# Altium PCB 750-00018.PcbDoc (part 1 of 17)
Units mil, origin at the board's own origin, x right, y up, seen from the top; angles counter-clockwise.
Board outline 7086.64 x 6299.21 mil, 8 copper layers (Top Layer, L2, L3, L4, L5, L6, L7, Bottom Layer), stack 60.6 mil thick; 1356 components, 1054 nets, 4851 pads, 4296 vias.
Unrouted connection lines stored in the file: 12.
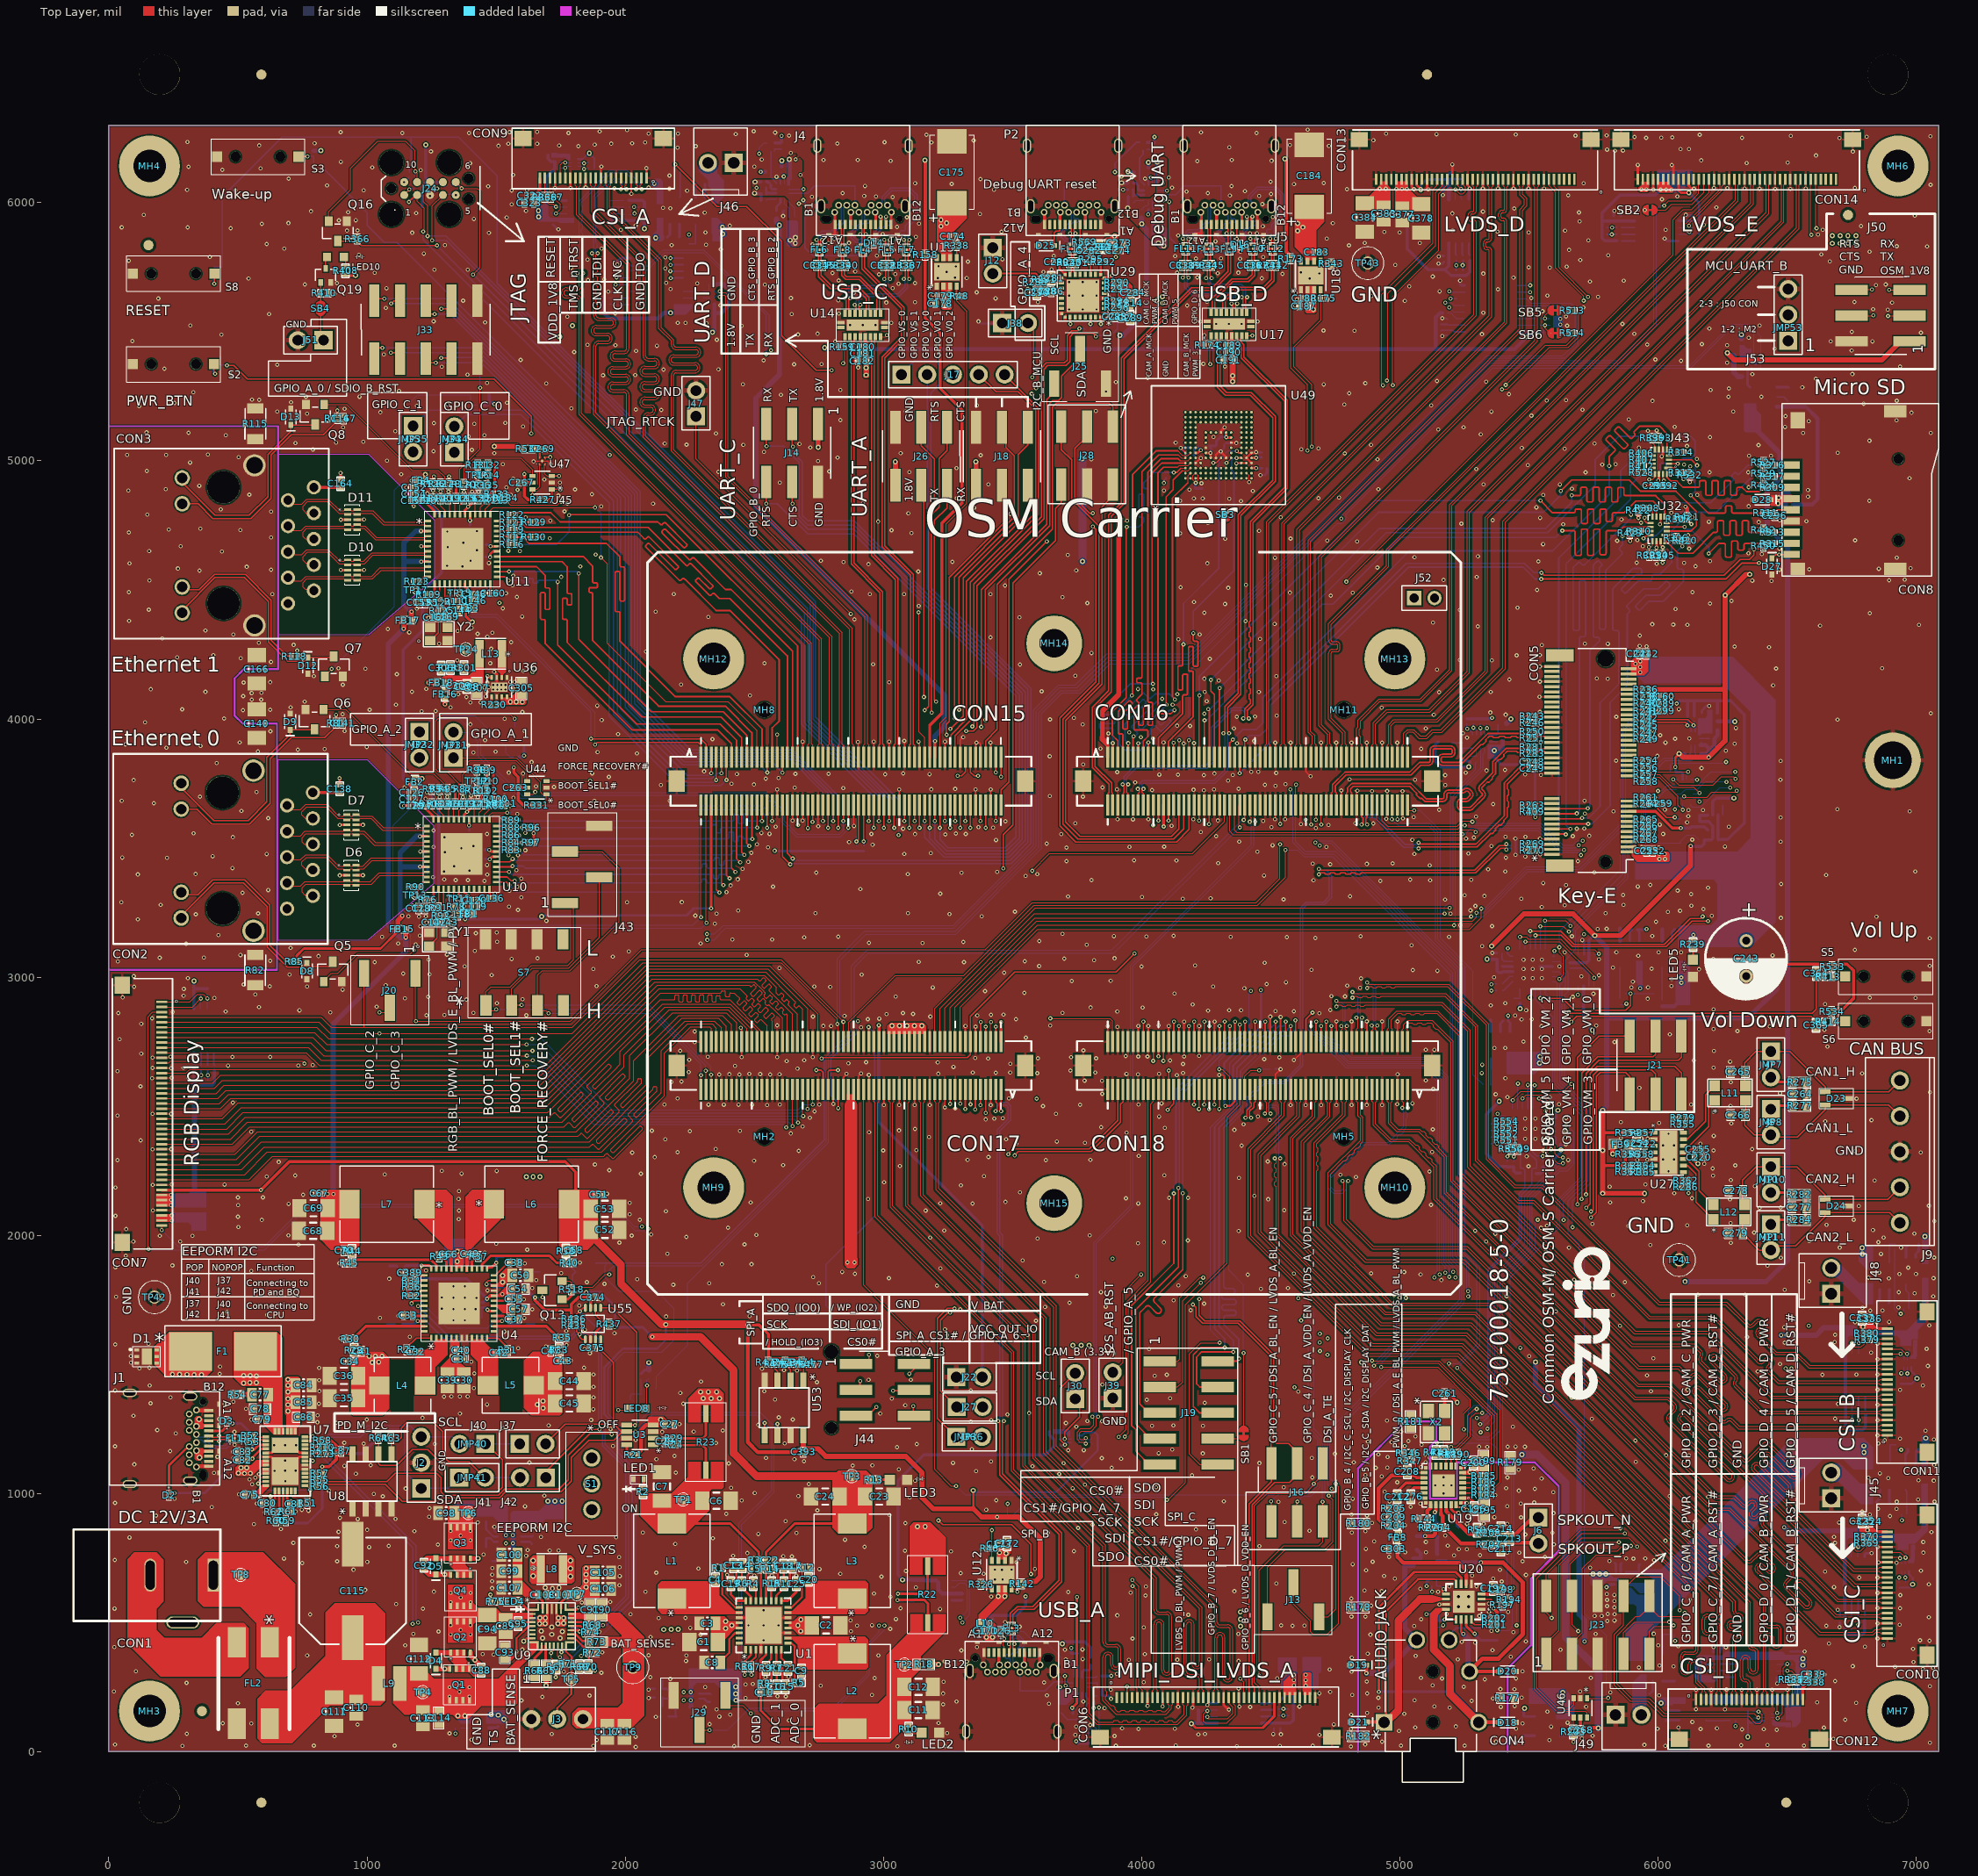
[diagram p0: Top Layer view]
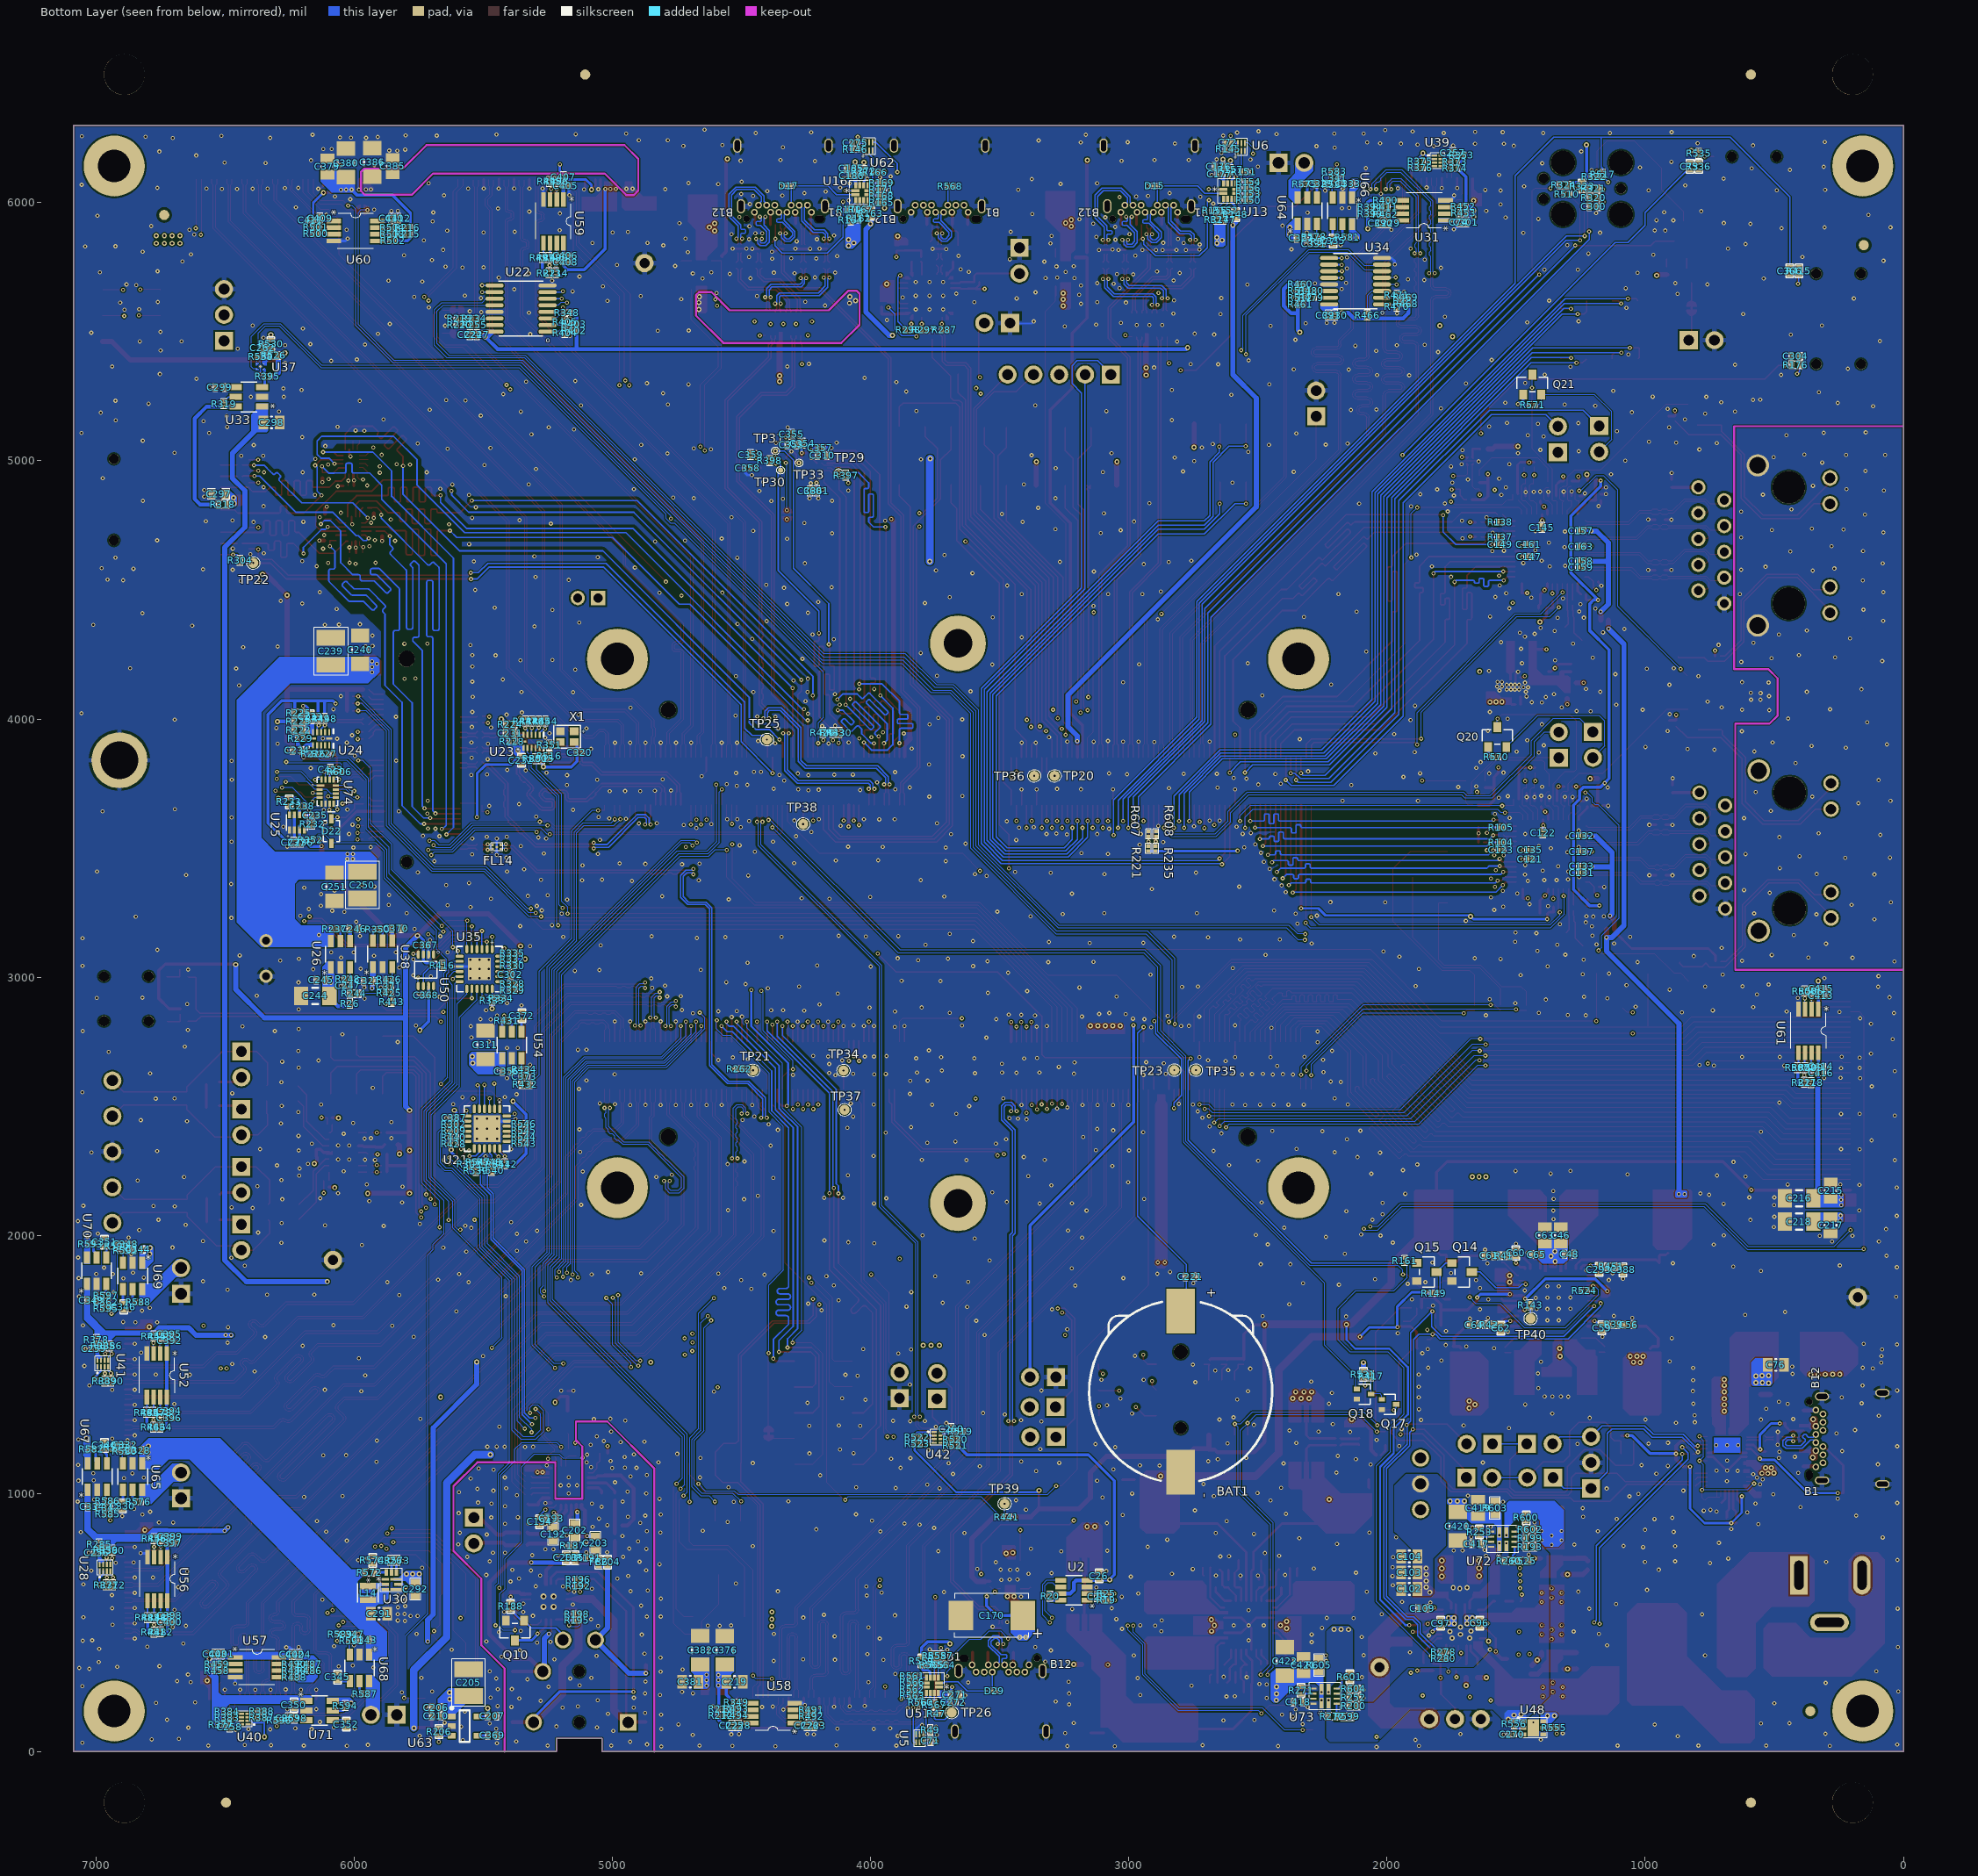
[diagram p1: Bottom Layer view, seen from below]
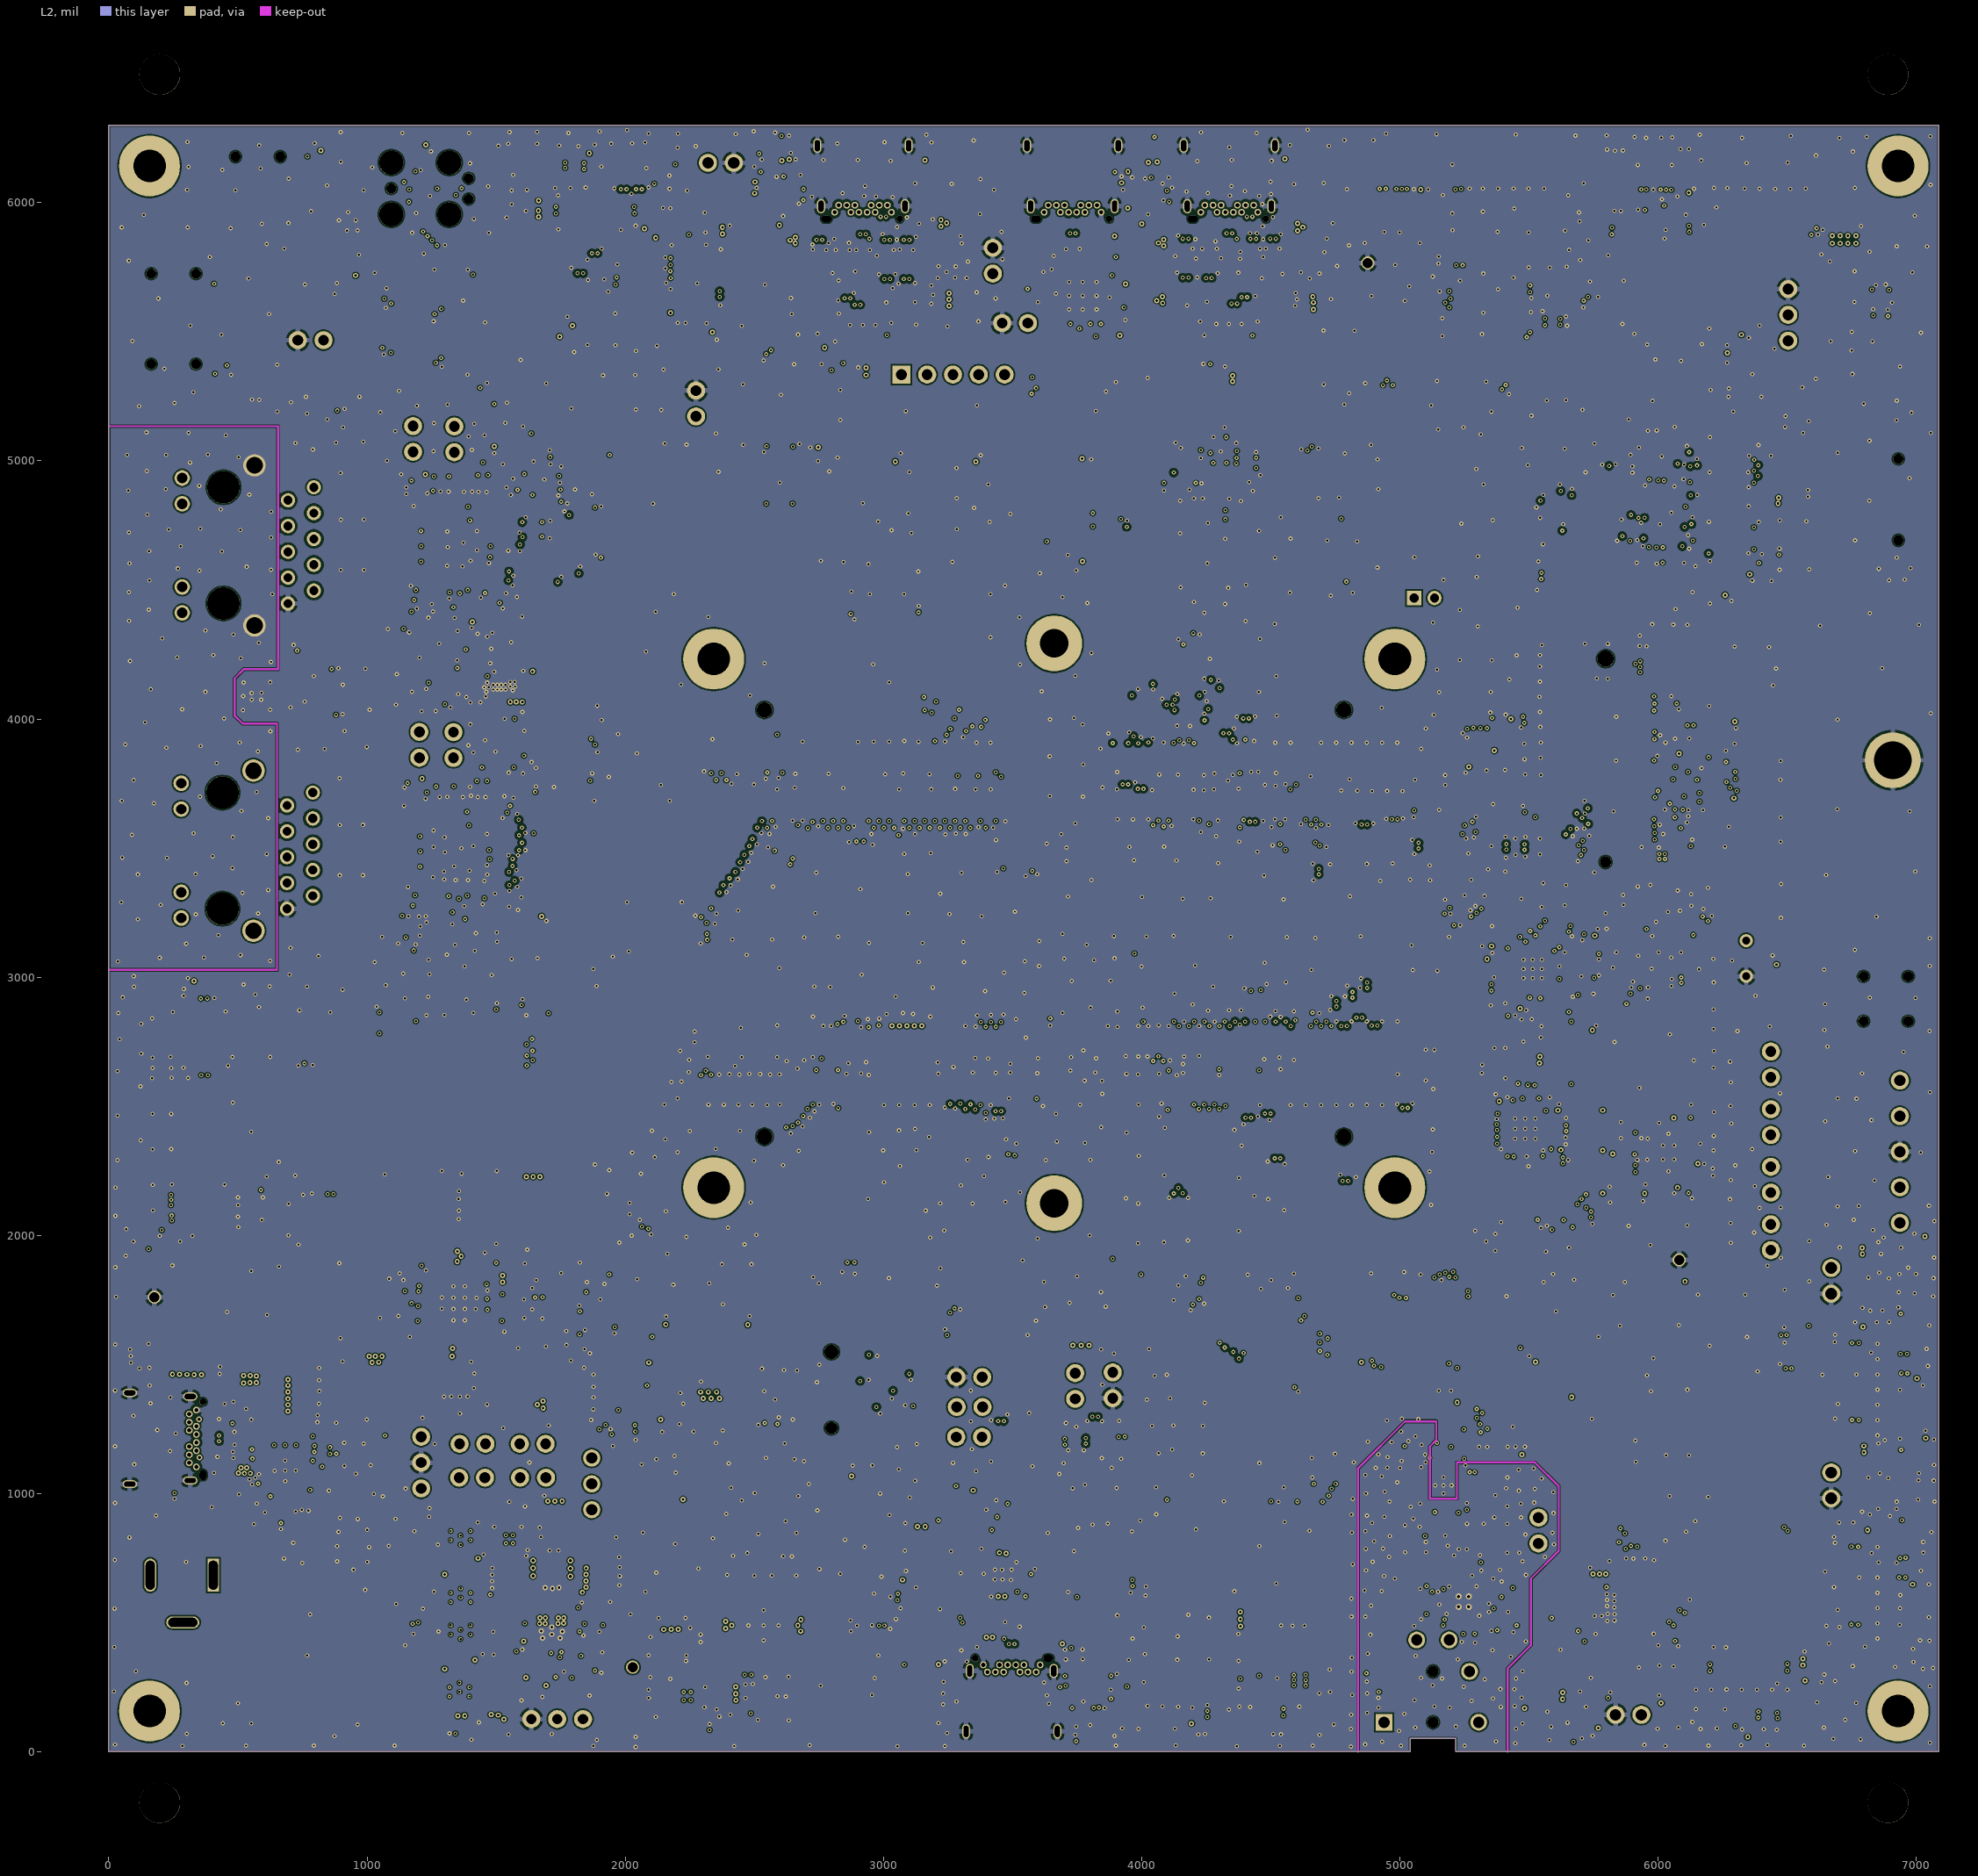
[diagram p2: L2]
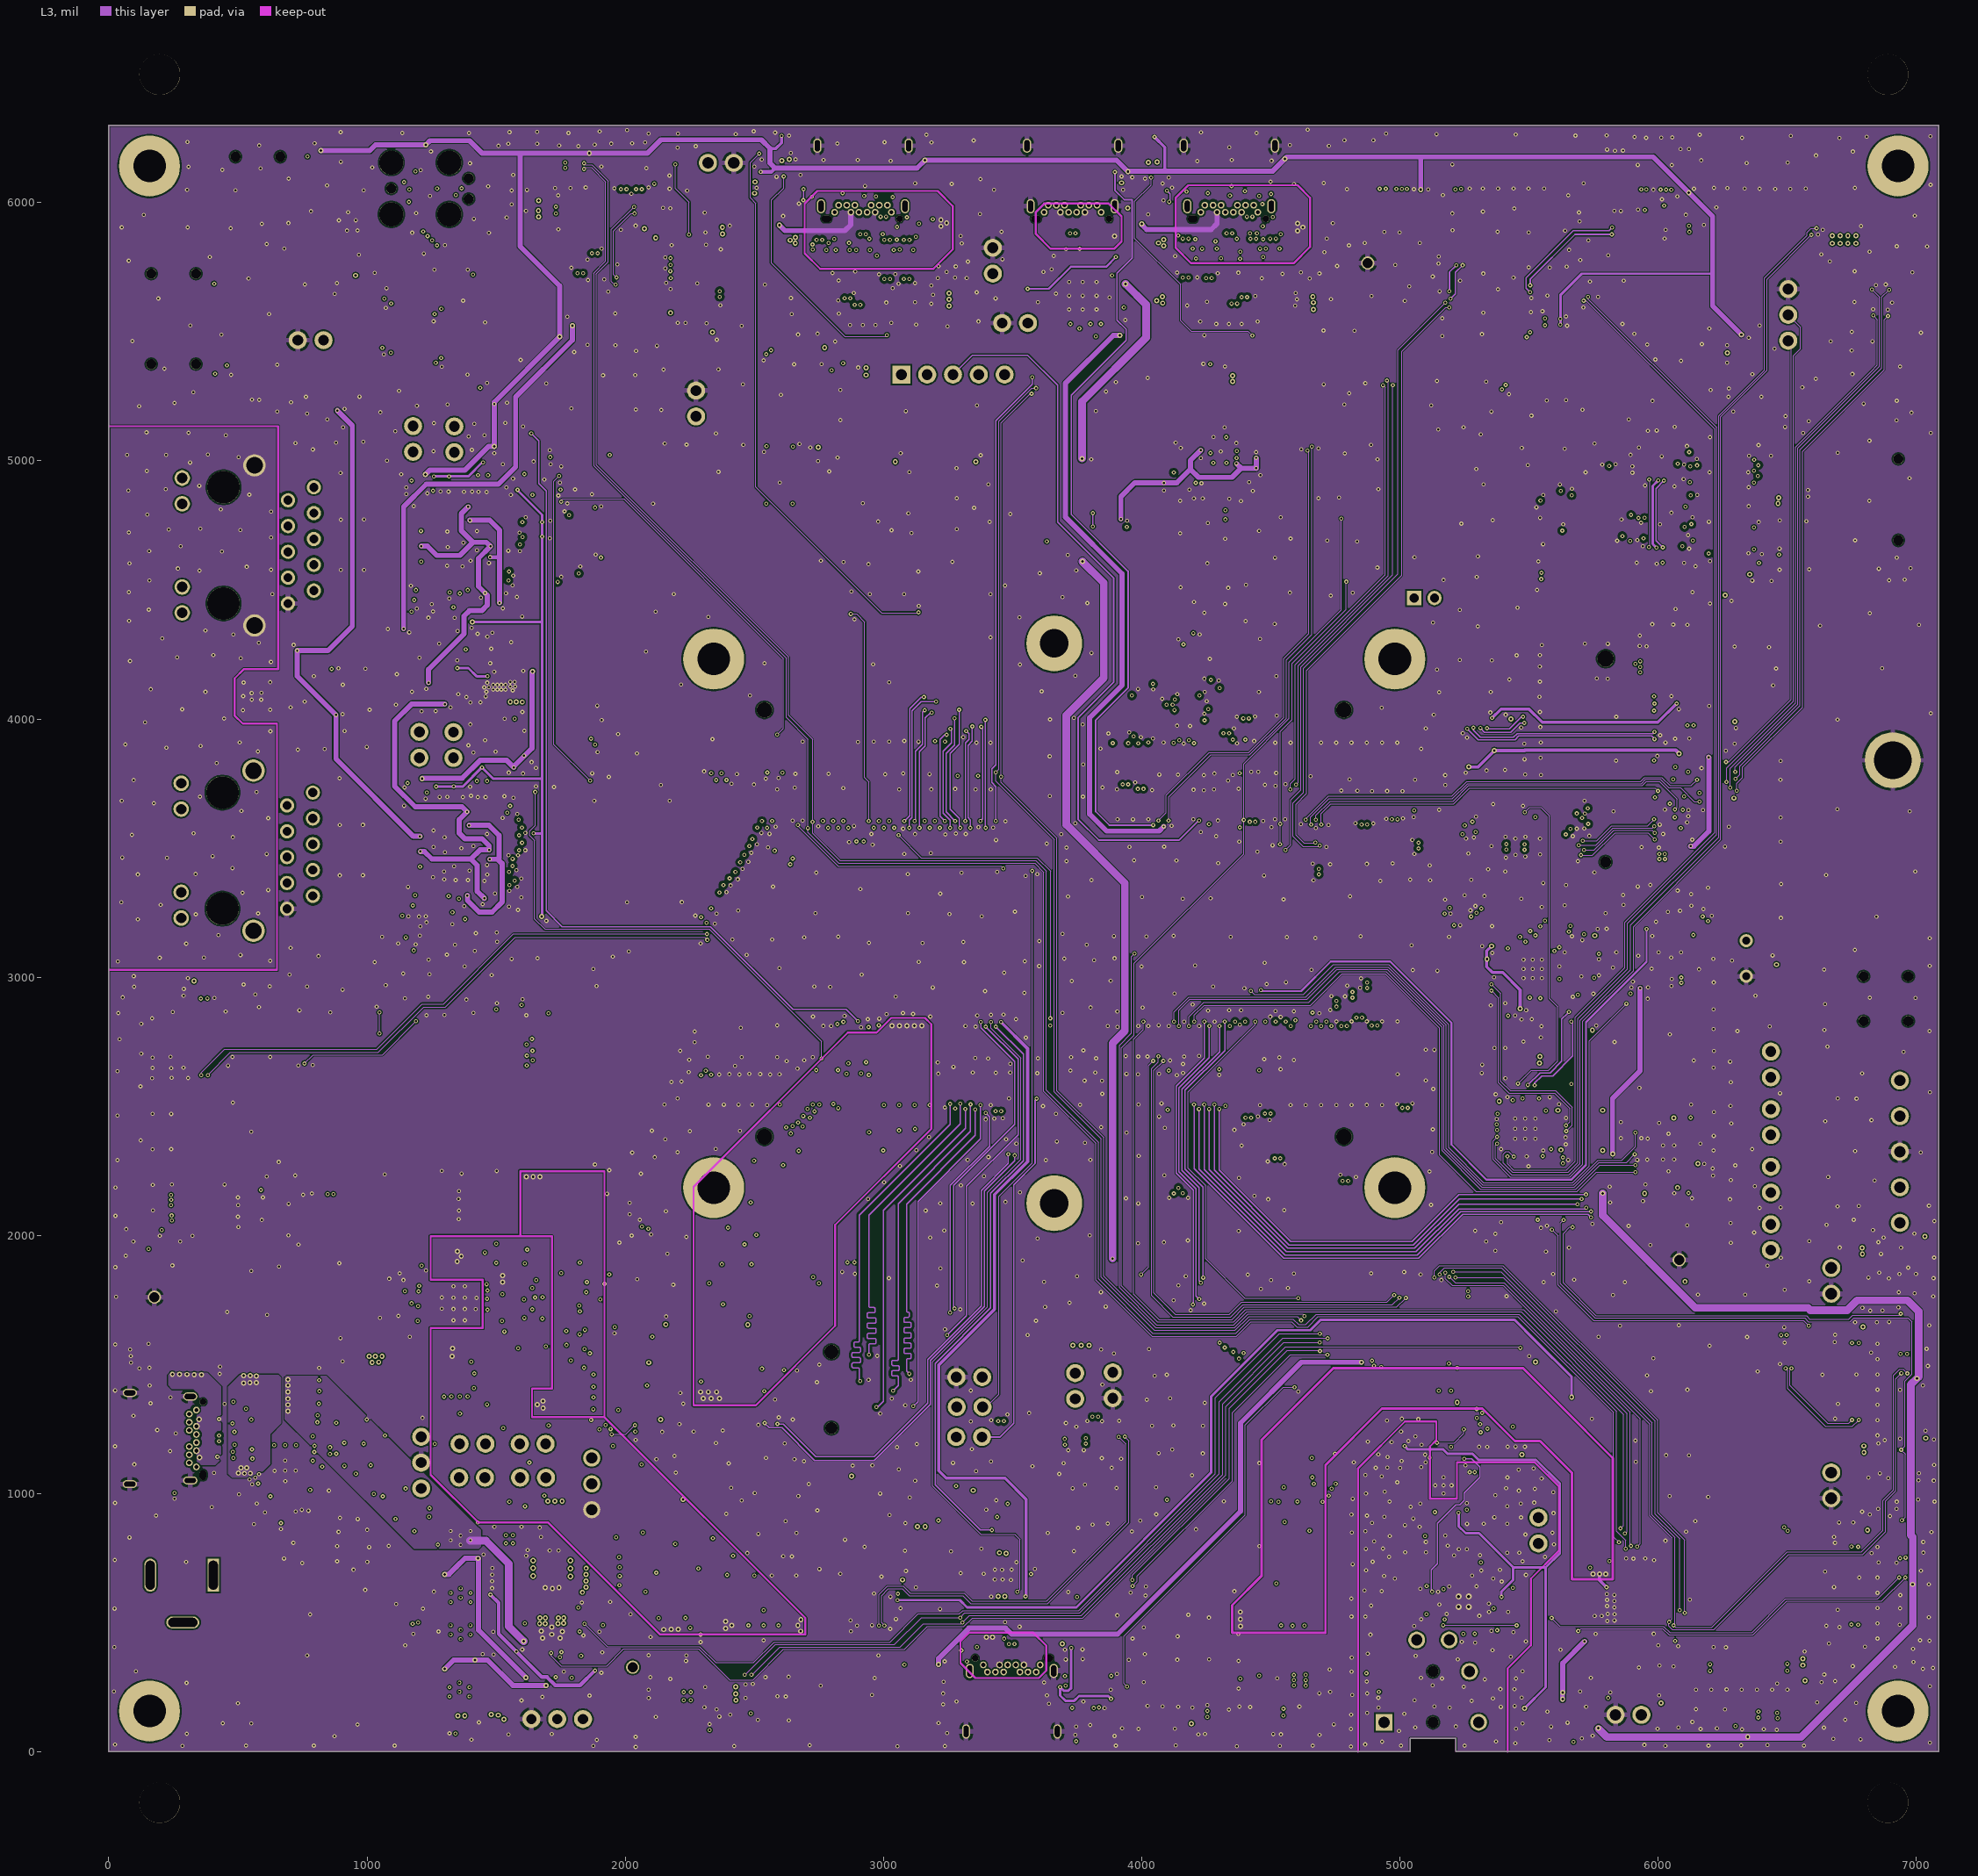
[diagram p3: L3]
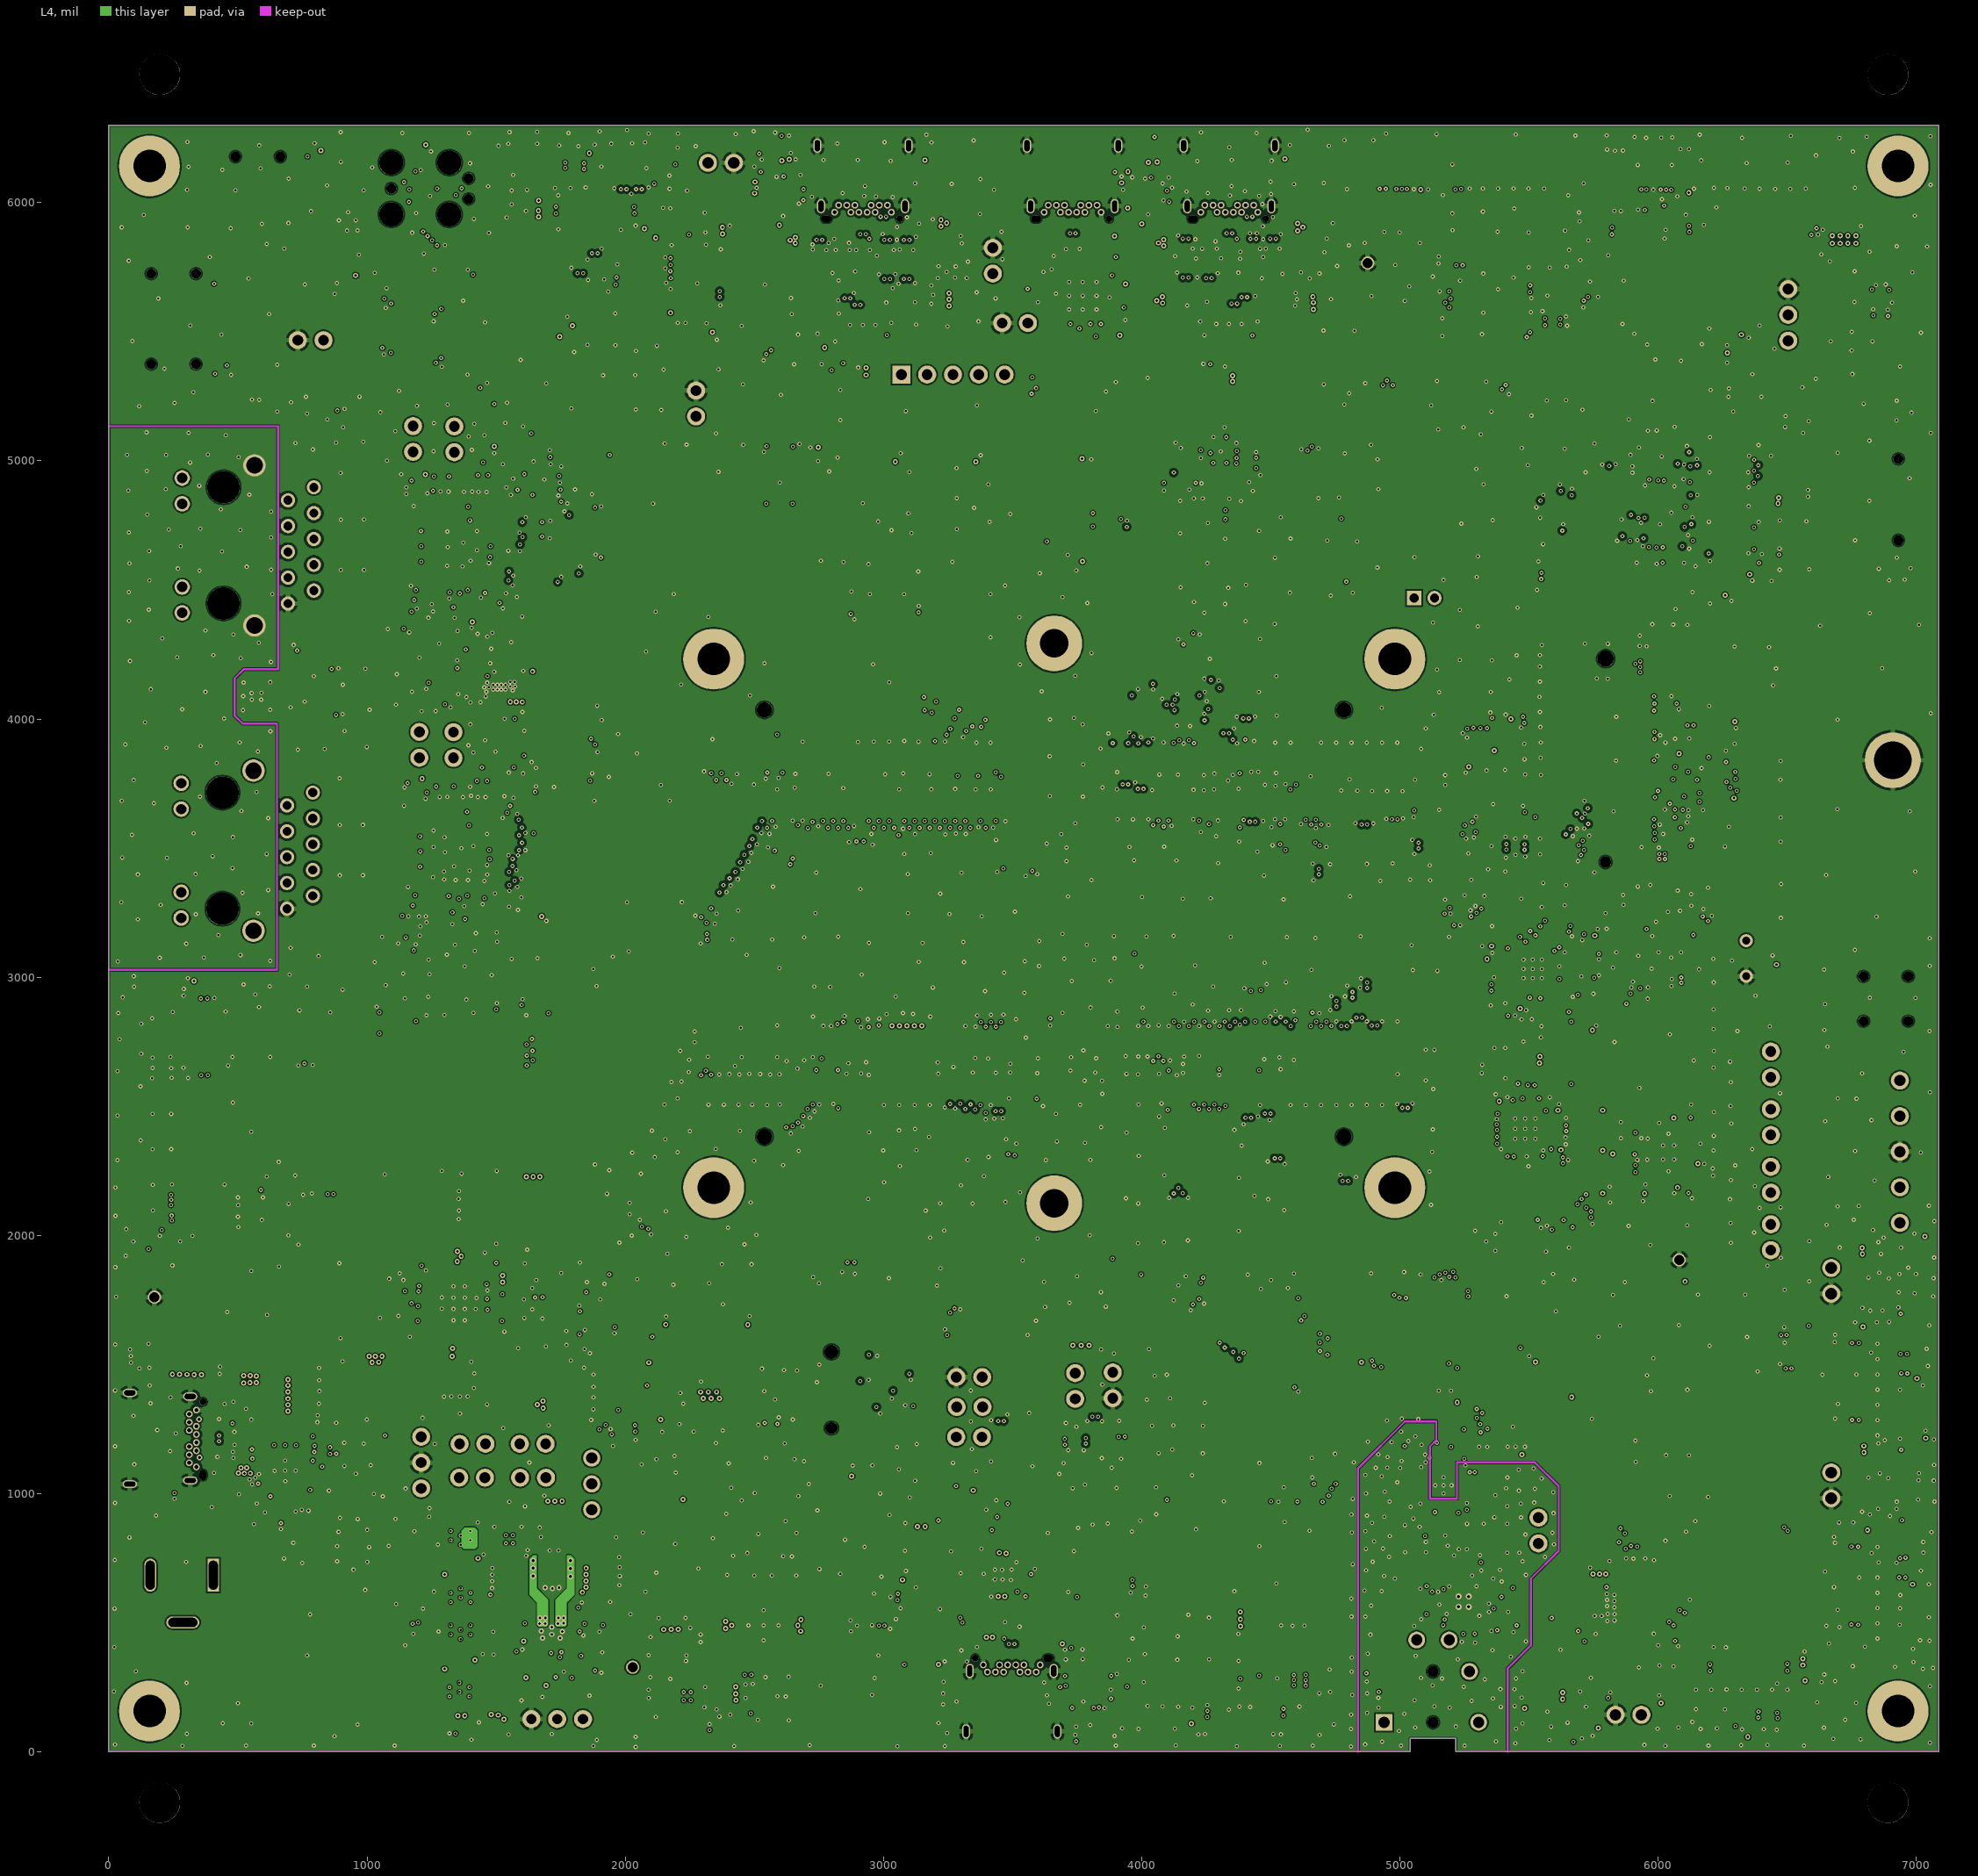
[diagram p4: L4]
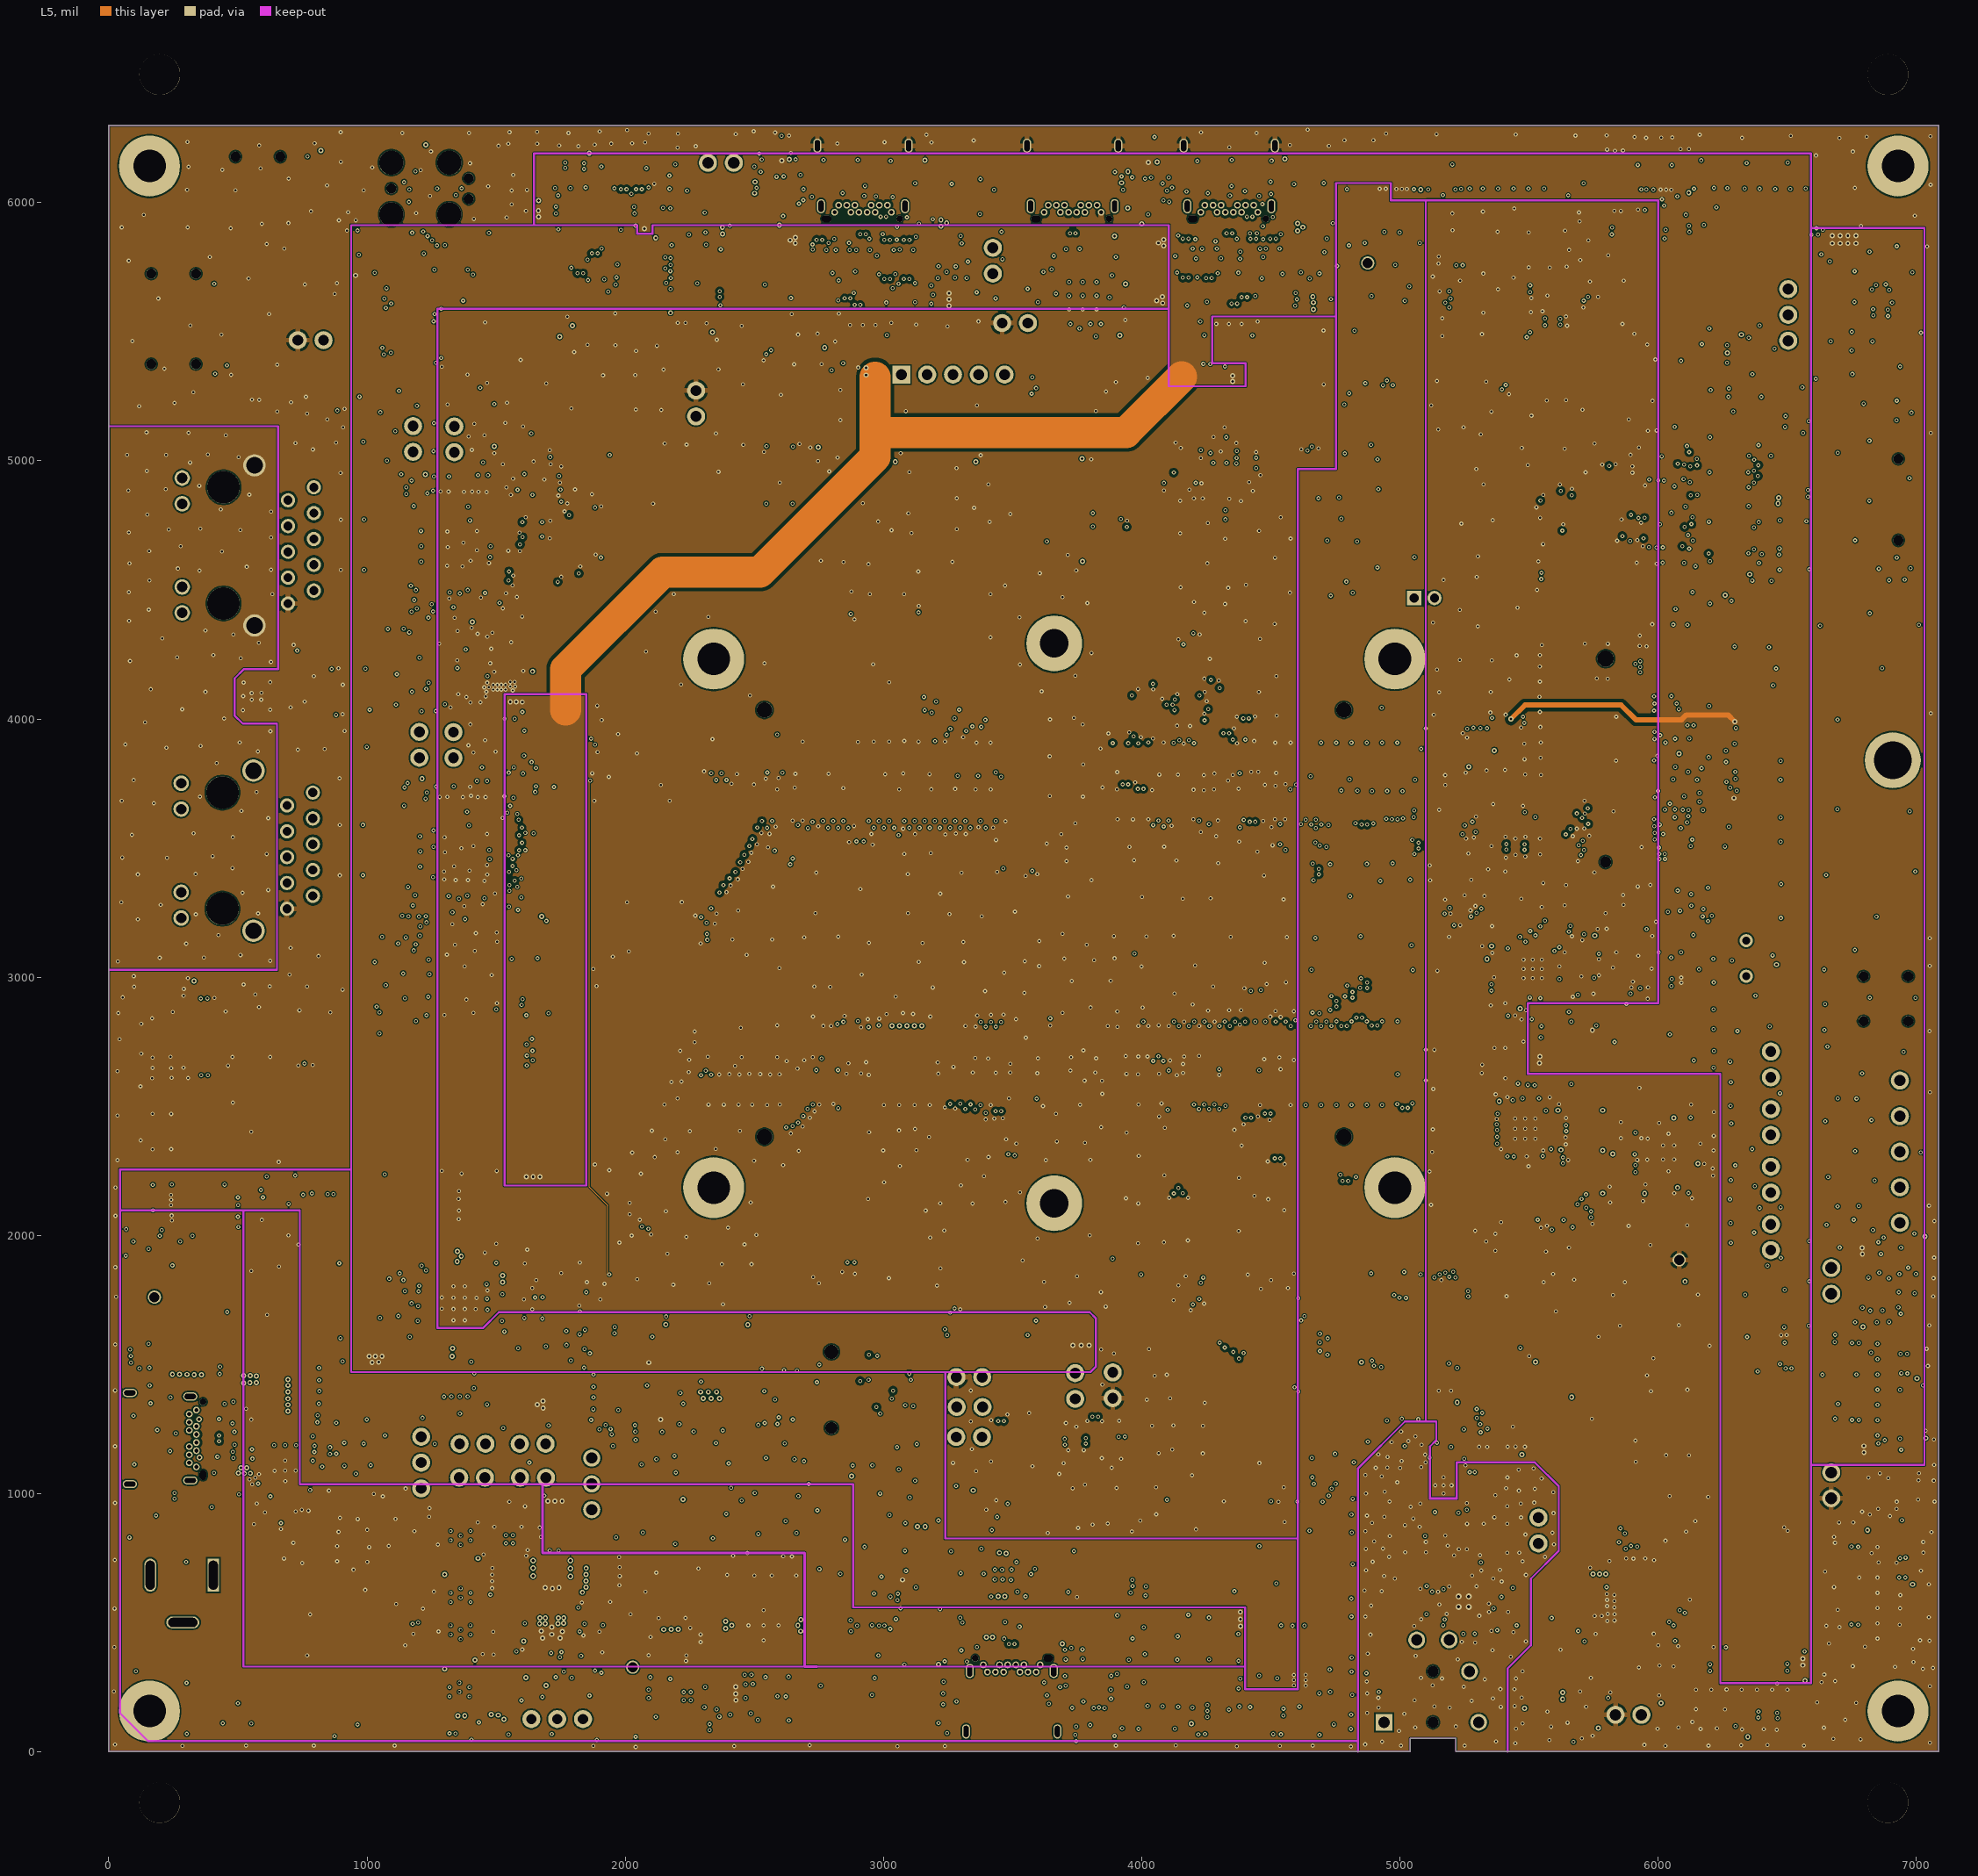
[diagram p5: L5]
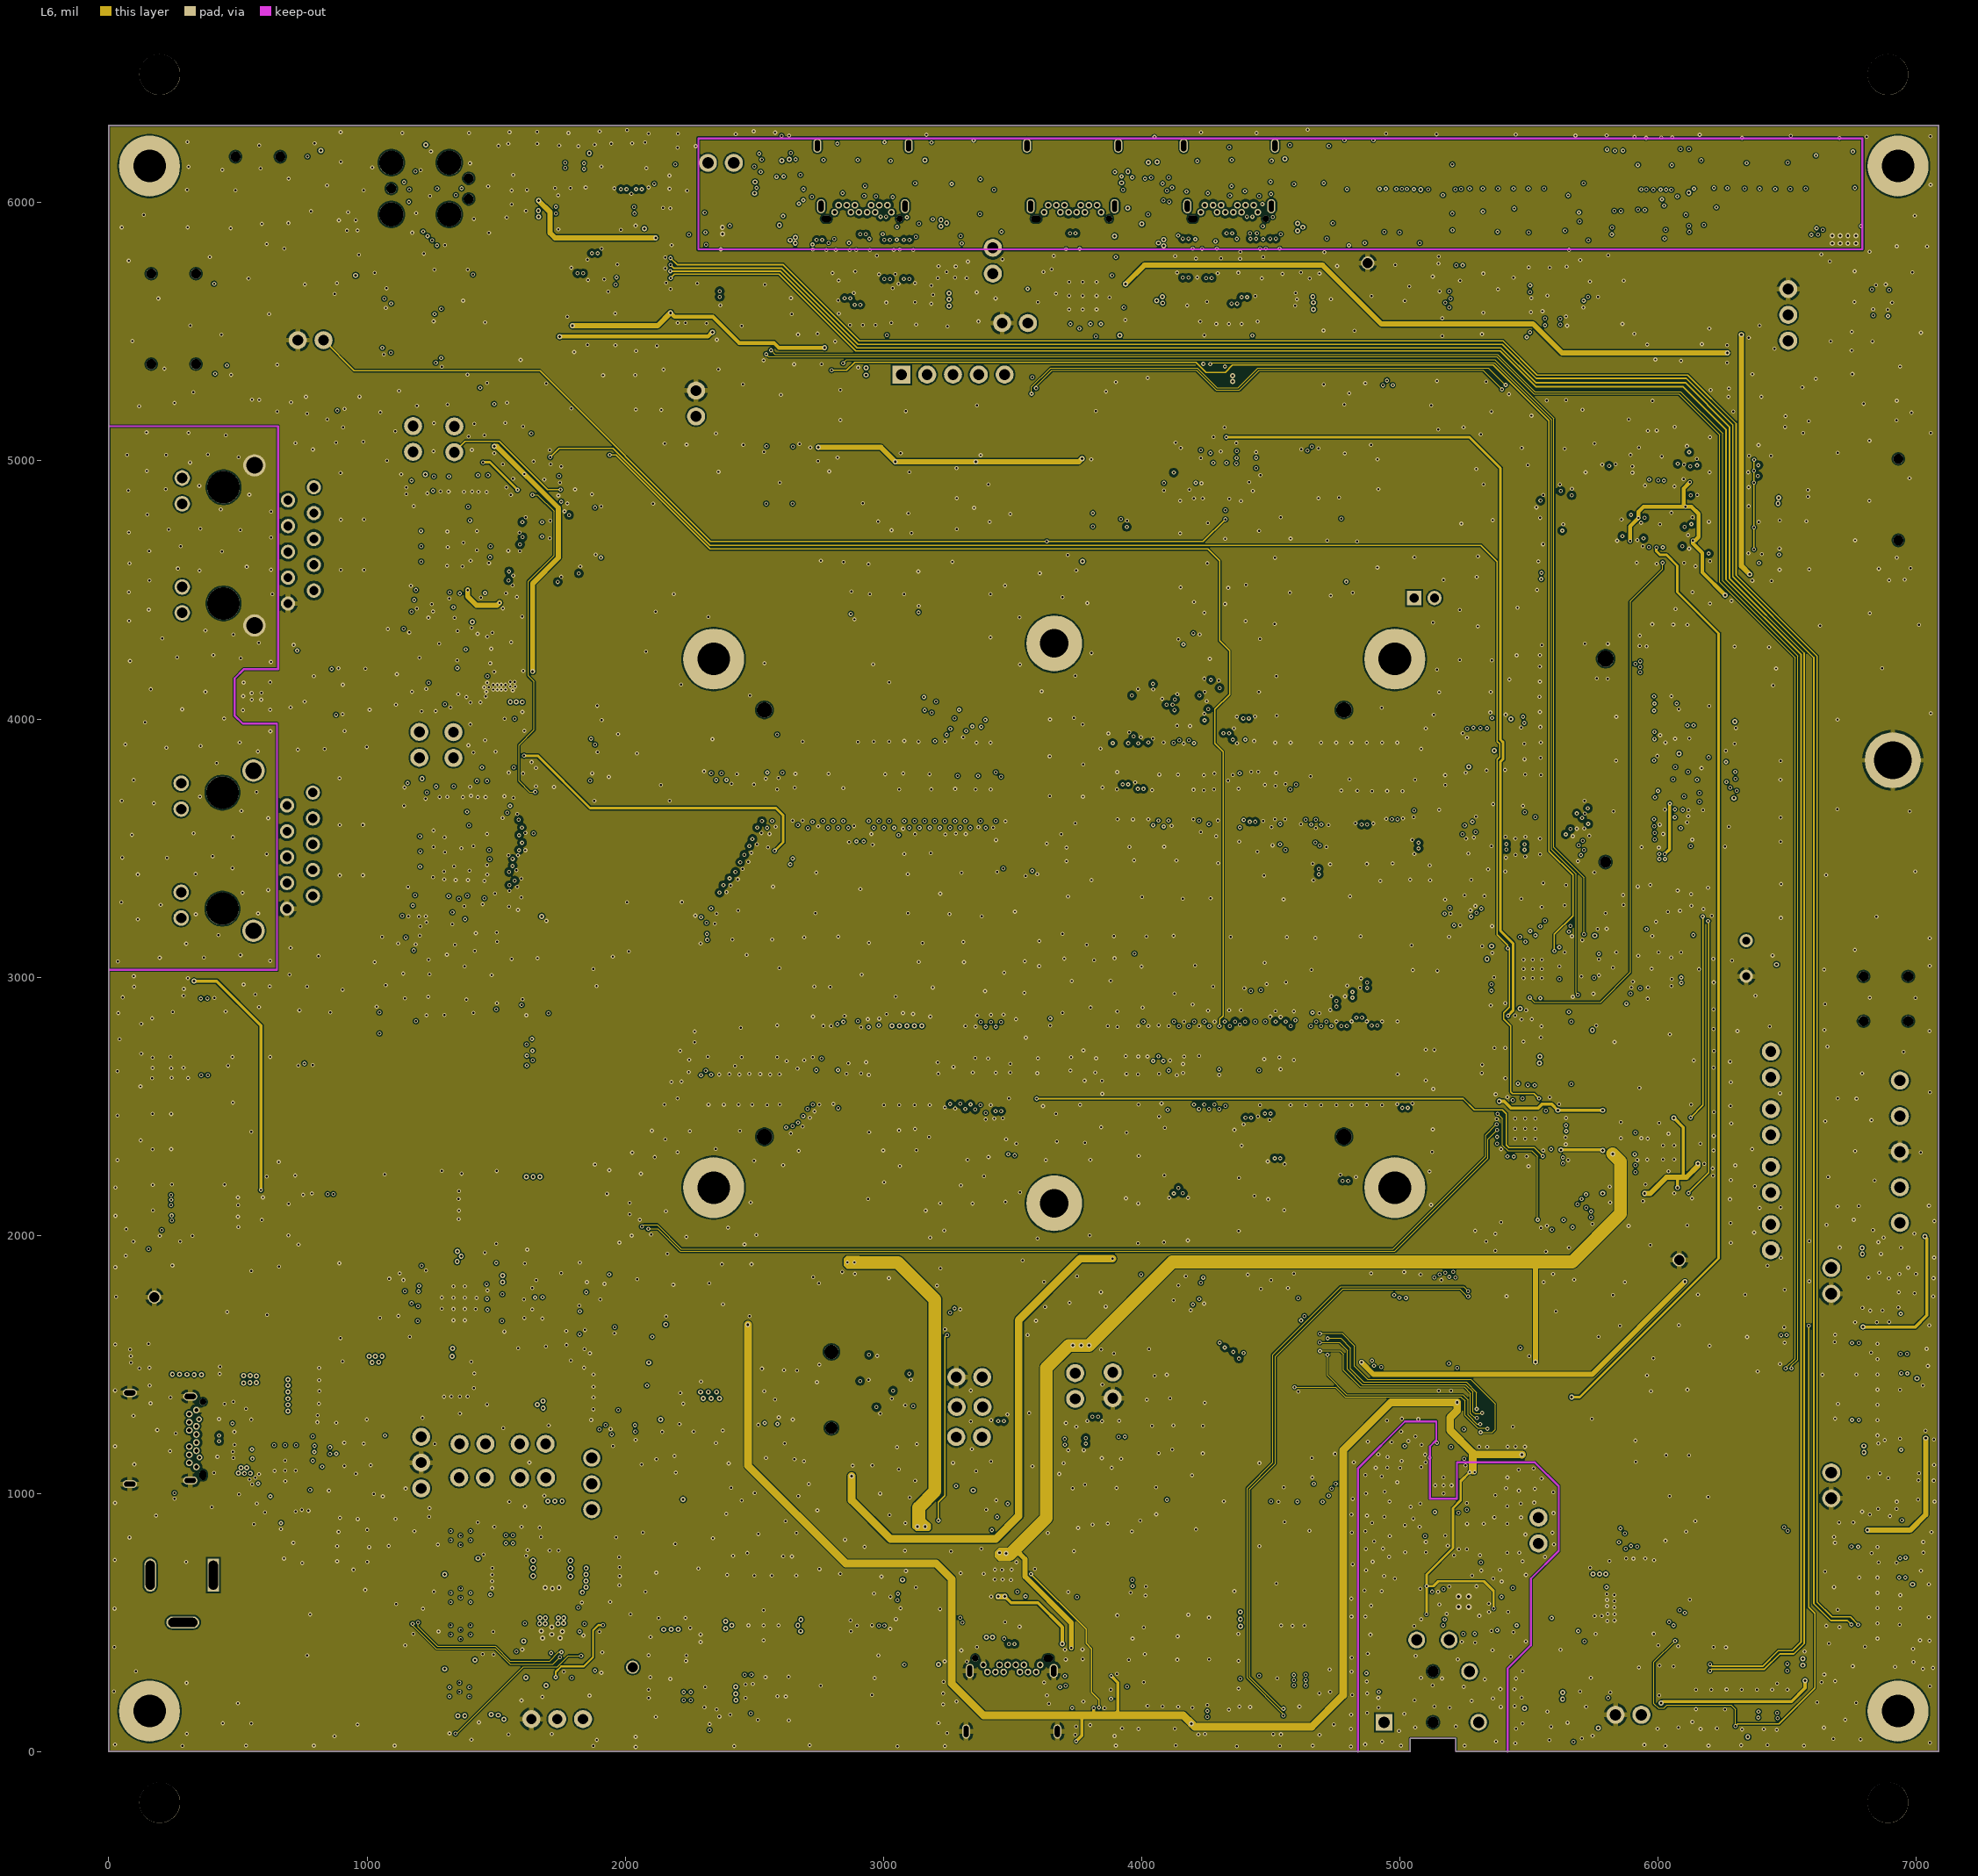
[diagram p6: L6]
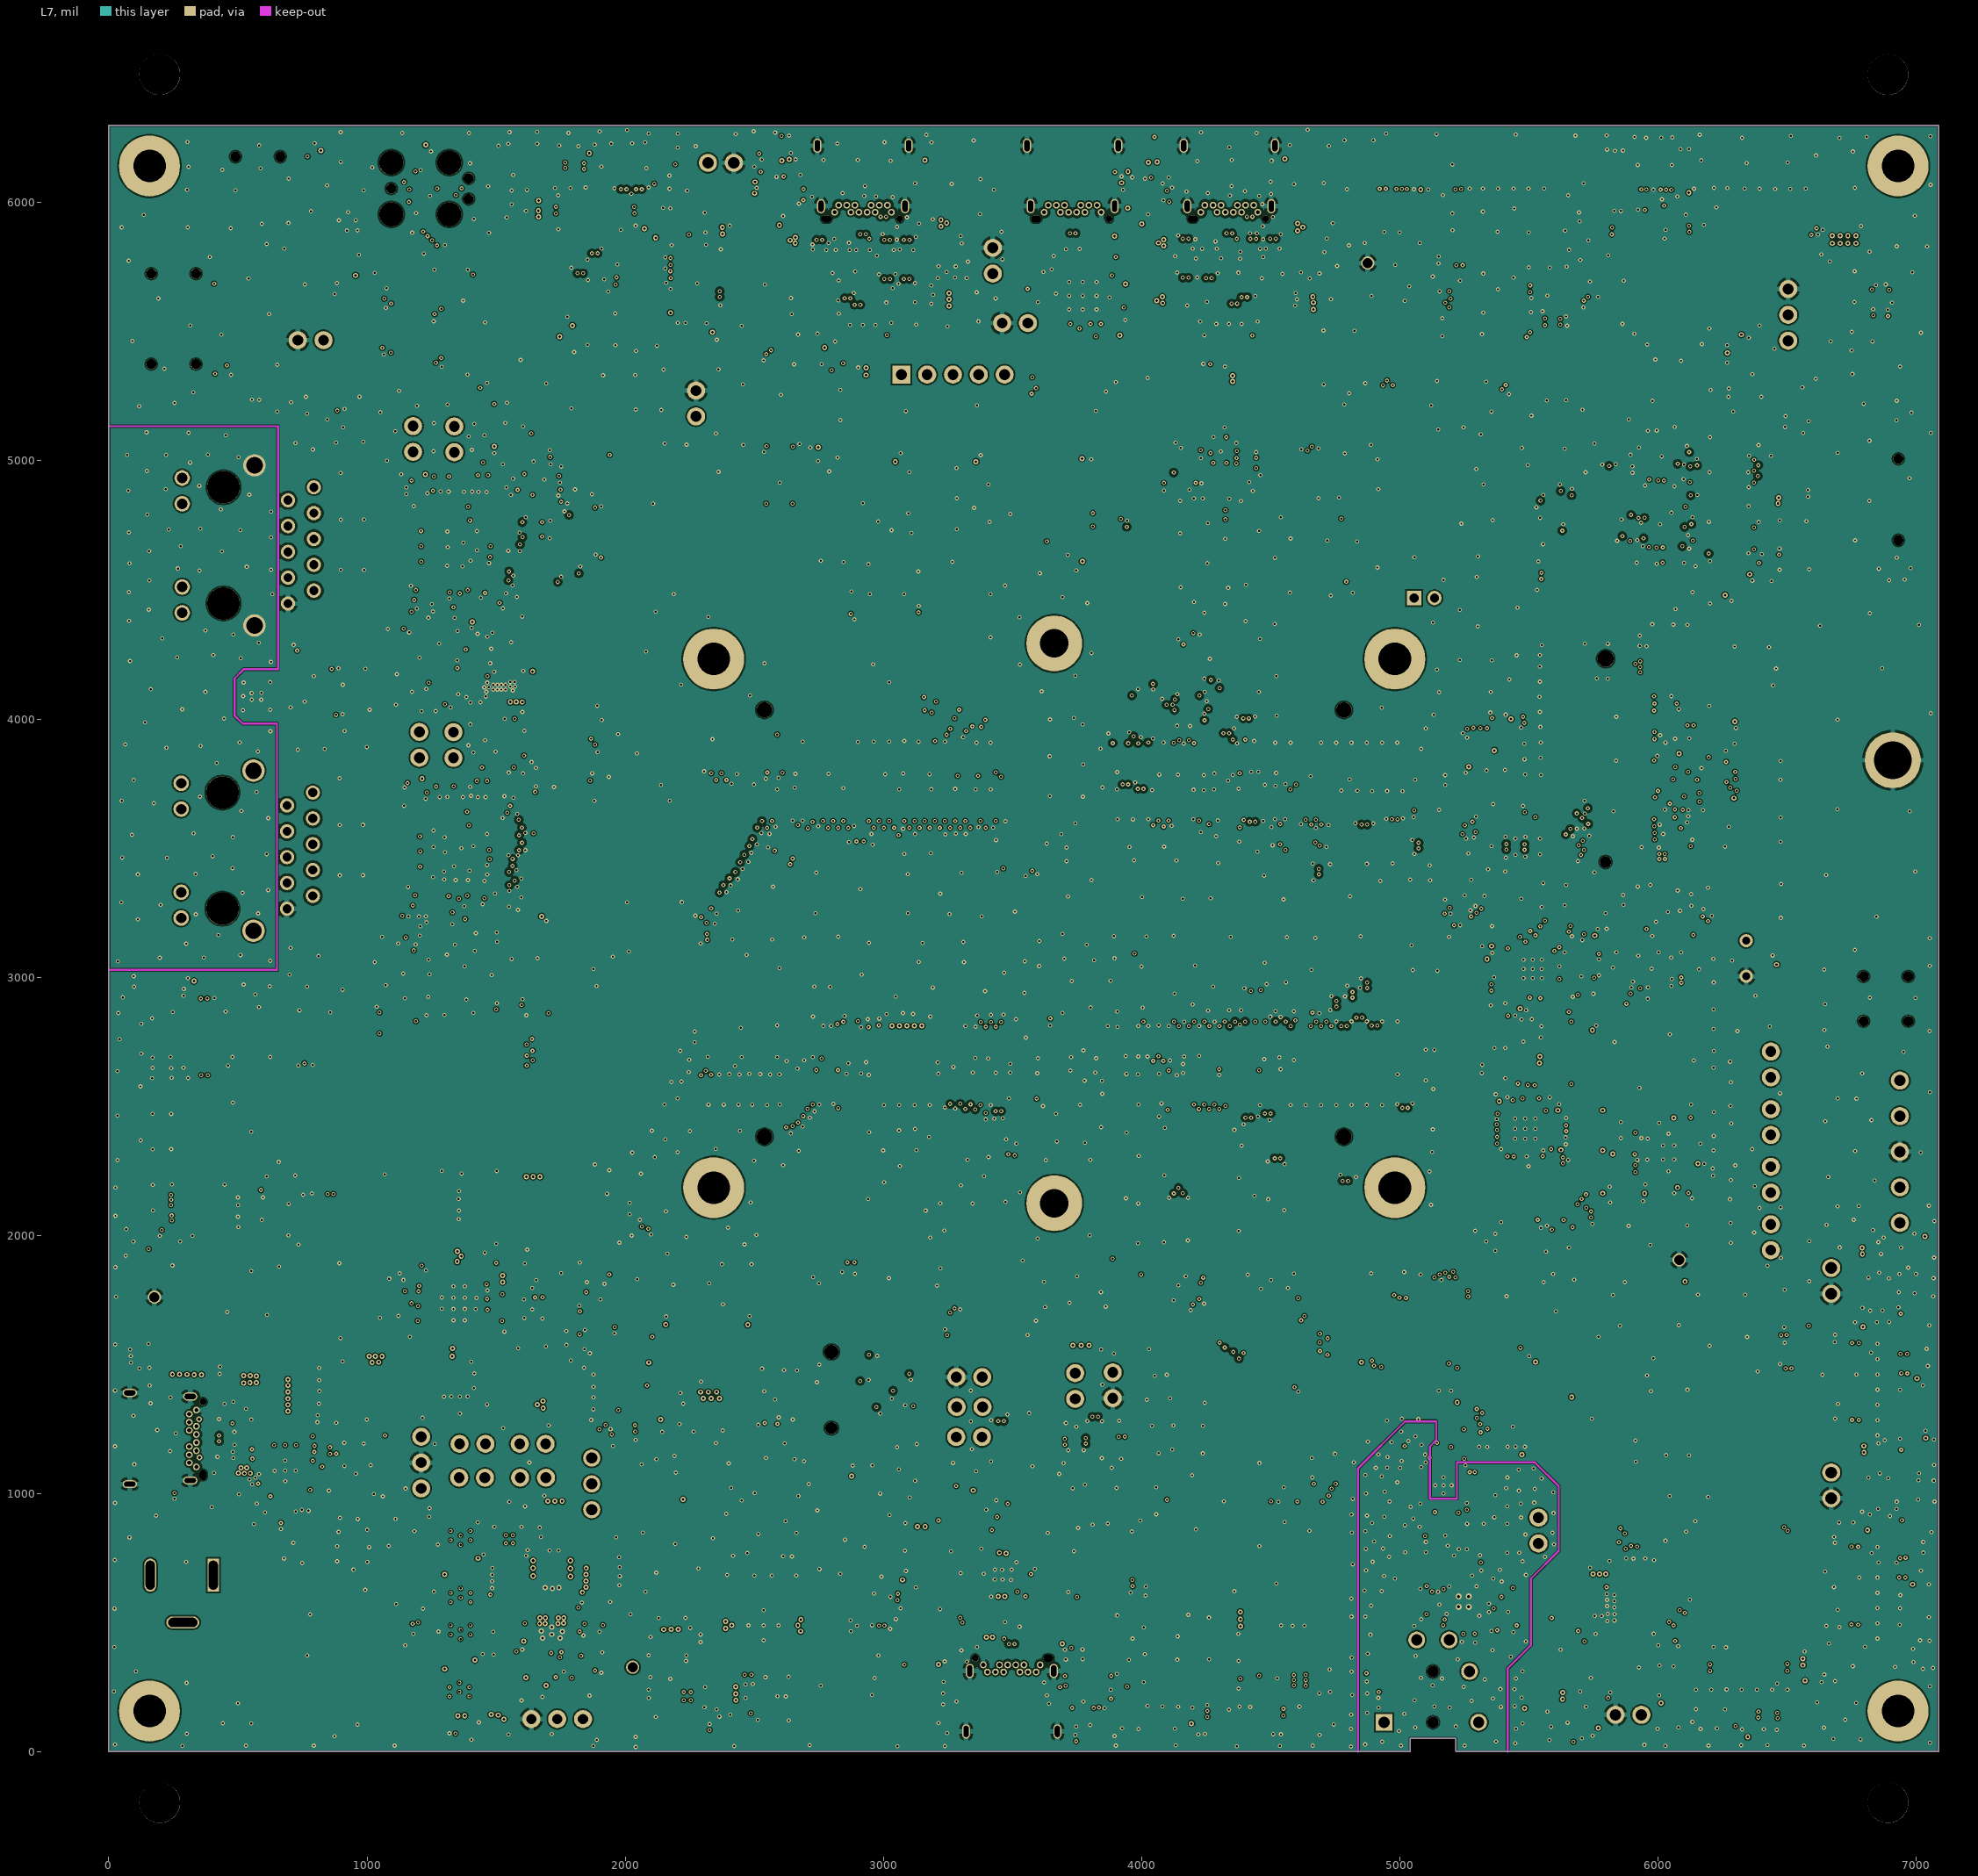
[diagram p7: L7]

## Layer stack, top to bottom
Top Solder: solder mask 0.8, SM-003, Dk 3.5
Top Layer: signal copper 1.4
Dielectric 1: prepreg 3.5, PP-013, Dk 3.78
L2: signal copper 1.4
Dielectric 3: prepreg 4.2, PP-016, Dk 3.87
L3: signal copper 1.4
Dielectric 2: prepreg 7, PP-008, Dk 3.73
L4: signal copper 1.4
Dielectric3: core 20, Core-015, Dk 4
L5: signal copper 1.4
Dielectric5: prepreg 7, PP-008, Dk 3.73
L6: signal copper 1.4
Dielectric 4: prepreg 4.2, PP-016, Dk 3.87
L7: signal copper 1.4
Dielectric4: prepreg 3.5, PP-013, Dk 3.78
Bottom Layer: signal copper 1.4
Bottom Solder: solder mask 0.8, SM-003, Dk 3.5

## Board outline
0,0 0,6299.21 7086.63,6299.21 7086.63,0 5216.45,0 5216.45,51.18 5039.28,51.18 5039.28,0

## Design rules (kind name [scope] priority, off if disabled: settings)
Clearance L3_VDD_3V3 [InNet('VDD_3V3') AND OnLayer('L5') vs InPolygon] p1: gap=4 ignorepadtopadclearanceinfootprint=TRUE except(4.02: THPad-Via THPad-Fill THPad-Poly THPad-Region; 15: Track-Poly)
Clearance Clearance_SPI [InNetClass('SPI_A') OR InNetClass('SPI_B') OR InNetClass('SPI_C') vs InPolygon] p2: gap=4 ignorepadtopadclearanceinfootprint=TRUE except(10: Arc-Fill Arc-Poly Arc-Region Track-Fill Track-Poly Track-Region SMDPad-Fill SMDPad-Poly SMDPad-Region THPad-Fill THPad-Poly THPad-Region Via-Fill Via-Poly Via-Region Fill-Fill Fill-Poly Fill-Region Poly-Poly Poly-Region Region-Region)
Clearance Clearance_EMMC [InNetClass('EMMC') vs InPolygon] p3: gap=4 ignorepadtopadclearanceinfootprint=TRUE except(10: Arc-Fill Arc-Poly Arc-Region Track-Fill Track-Poly Track-Region SMDPad-Fill SMDPad-Poly SMDPad-Region THPad-Fill THPad-Poly THPad-Region Via-Fill Via-Poly Via-Region Fill-Fill Fill-Poly Fill-Region Poly-Poly Poly-Region Region-Region)
Clearance Clearance_DIFF [InAnyDifferentialPair vs InPolygon] p4: gap=4 ignorepadtopadclearanceinfootprint=TRUE except(8: Arc-Fill Arc-Poly Arc-Region Track-Fill Track-Poly Track-Region SMDPad-Fill SMDPad-Poly SMDPad-Region; 10: THPad-Fill THPad-Poly THPad-Region Via-Fill Via-Poly Via-Region Fill-Fill Fill-Poly Fill-Region Poly-Poly Poly-Region Region-Region)
Clearance Clearance_ETH [InNetClass('ETH_ALL') vs InPolygon] p5: gap=4 ignorepadtopadclearanceinfootprint=TRUE except(10: Arc-Fill Arc-Poly Arc-Region Track-Fill Track-Poly Track-Region SMDPad-Fill SMDPad-Poly SMDPad-Region THPad-Fill THPad-Poly THPad-Region Via-Fill Via-Poly Via-Region Fill-Fill Fill-Poly Fill-Region Poly-Poly Poly-Region Region-Region)
Clearance Clearance_SDIO [InNetClass('SDIO_ALL') vs InPolygon] p6: gap=4 ignorepadtopadclearanceinfootprint=TRUE except(10: SMDPad-Fill SMDPad-Poly SMDPad-Region THPad-Fill THPad-Poly THPad-Region Via-Fill Via-Poly Via-Region Fill-Fill Fill-Poly Fill-Region Poly-Poly Poly-Region Region-Region; 12: Arc-Fill Arc-Poly Arc-Region Track-Fill Track-Poly Track-Region)
Clearance Clearance_U49 [InComponent('U49')] p7: gap=3 ignorepadtopadclearanceinfootprint=TRUE
Clearance [All] p8: gap=4 ignorepadtopadclearanceinfootprint=TRUE except(4.02: THPad-Via; 6: THPad-Fill THPad-Poly THPad-Region Fill-Hole Poly-Hole Region-Hole)
DiffPairsRouting DIFF_85 [InDifferentialPairClass('85 ohm')] p1: maxlimit=5 minlimit=5 mostfreqgap=5 toplayer_minwidth=6 toplayer_maxwidth=6 toplayer_prefwidth=6 midlayer1_minwidth=4.03 midlayer1_maxwidth=4.03 midlayer1_prefwidth=4.03 midlayer2_minwidth=6 midlayer2_maxwidth=6 midlayer2_prefwidth=6 midlayer3_minwidth=6 midlayer3_maxwidth=6 midlayer3_prefwidth=6 midlayer4_minwidth=3.08 midlayer4_maxwidth=3.08 midlayer4_prefwidth=3.08 midlayer5_minwidth=4.03 midlayer5_maxwidth=4.03 midlayer5_prefwidth=4.03 midlayer6_minwidth=3.08 midlayer6_maxwidth=3.08 midlayer6_prefwidth=3.08 bottomlayer_minwidth=6 bottomlayer_maxwidth=6 bottomlayer_prefwidth=6 impedanceprofiledriven=TRUE impedanceprofileid={79A27EAB-447E-42FA-B11E-89F2876D32F2} impedanceprofilevalue=85.000000 maxuncoupledlength=500
DiffPairsRouting DIFF_90 [InDifferentialPairClass('90 ohm')] p2: maxlimit=6.5 minlimit=5 mostfreqgap=6.5 toplayer_maxgap=5 toplayer_prefgap=5 toplayer_minwidth=5 toplayer_maxwidth=5 toplayer_prefwidth=5 midlayer1_maxgap=5 midlayer1_prefgap=5 midlayer1_minwidth=3.41 midlayer1_maxwidth=3.41 midlayer1_prefwidth=3.41 midlayer2_mingap=6.5 midlayer2_minwidth=6.5 midlayer2_maxwidth=6.5 midlayer2_prefwidth=6.5 midlayer3_mingap=6.5 midlayer3_minwidth=6.5 midlayer3_maxwidth=6.5 midlayer3_prefwidth=6.5 midlayer4_maxgap=5 midlayer4_prefgap=5 midlayer4_minwidth=2.62 midlayer4_maxwidth=2.62 midlayer4_prefwidth=2.62 midlayer5_maxgap=5 midlayer5_prefgap=5 midlayer5_minwidth=3.41 midlayer5_maxwidth=3.41 midlayer5_prefwidth=3.41 midlayer6_maxgap=5 midlayer6_prefgap=5 midlayer6_minwidth=2.62 midlayer6_maxwidth=2.62 midlayer6_prefwidth=2.62 bottomlayer_maxgap=5 bottomlayer_prefgap=5 bottomlayer_minwidth=5 bottomlayer_maxwidth=5 bottomlayer_prefwidth=5 impedanceprofiledriven=TRUE impedanceprofileid={CF8262DC-DA5D-4CA2-AD45-F32DD7707F8D} impedanceprofilevalue=90.000000 maxuncoupledlength=500
DiffPairsRouting DIFF_100 [InDifferentialPairClass('100 ohm')] p3: maxlimit=6.5 minlimit=5 mostfreqgap=6.5 toplayer_mingap=5.5 toplayer_maxgap=5.5 toplayer_prefgap=5.5 toplayer_minwidth=4 toplayer_maxwidth=4 toplayer_prefwidth=4 midlayer1_maxgap=5 midlayer1_prefgap=5 midlayer1_minwidth=2.4 midlayer1_maxwidth=2.4 midlayer1_prefwidth=2.4 midlayer2_mingap=6.5 midlayer2_minwidth=4.5 midlayer2_maxwidth=4.5 midlayer2_prefwidth=4.5 midlayer3_mingap=6.5 midlayer3_minwidth=4.5 midlayer3_maxwidth=4.5 midlayer3_prefwidth=4.5 midlayer4_maxgap=5 midlayer4_prefgap=5 midlayer4_minwidth=1.85 midlayer4_maxwidth=1.85 midlayer4_prefwidth=1.85 midlayer5_maxgap=5 midlayer5_prefgap=5 midlayer5_minwidth=2.4 midlayer5_maxwidth=2.4 midlayer5_prefwidth=2.4 midlayer6_maxgap=5 midlayer6_prefgap=5 midlayer6_minwidth=1.85 midlayer6_maxwidth=1.85 midlayer6_prefwidth=1.85 bottomlayer_mingap=5.5 bottomlayer_maxgap=5.5 bottomlayer_prefgap=5.5 bottomlayer_minwidth=4 bottomlayer_maxwidth=4 bottomlayer_prefwidth=4 impedanceprofiledriven=TRUE impedanceprofileid={D3BBAF9F-DC67-4CF2-A020-BBB0924F39E5} impedanceprofilevalue=100.000000 maxuncoupledlength=500
HoleSize [All] p1: absolutevalues=TRUE maxlimit=393.7 minlimit=1 maxpercent=80.000 minpercent=20.000
MatchedLengths CSI_A_Class [InNetClass('Class_CSI_A')] p1: tolerance=1000 checknetsindiffpair=FALSE checkdiffpairvsdiffpair=TRUE checkxsignals=TRUE checkothers=TRUE usedelayunits=TRUE delaytolerance=0.500000
MatchedLengths CSI_B_Class [InNetClass('Class_CSI_B')] p2: tolerance=1000 checknetsindiffpair=FALSE checkdiffpairvsdiffpair=TRUE checkxsignals=TRUE checkothers=TRUE usedelayunits=TRUE delaytolerance=0.500000
MatchedLengths CSI_C_Class [InNetClass('Class_CSI_C')] p3: tolerance=1000 checknetsindiffpair=FALSE checkdiffpairvsdiffpair=TRUE checkxsignals=TRUE checkothers=TRUE usedelayunits=TRUE delaytolerance=0.500000
MatchedLengths CSI_D_Class [InNetClass('Class_CSI_D')] p4: tolerance=1000 checknetsindiffpair=FALSE checkdiffpairvsdiffpair=TRUE checkxsignals=TRUE checkothers=TRUE usedelayunits=TRUE delaytolerance=0.500000
MatchedLengths "MIPI_DSI_LVDS_A_ Class" [InNetClass('Class_MIPI_DSI_LVDS_A')] p5: tolerance=1000 checknetsindiffpair=FALSE checkdiffpairvsdiffpair=TRUE checkxsignals=TRUE checkothers=TRUE usedelayunits=TRUE delaytolerance=0.500000
MinimumSolderMaskSliver [All] p1 off: minsoldermaskwidth=10
PolygonConnect PolygonConnect_SMT [InComponentClass('SMT') vs InNet('GND')] p1: connectstyle=Relief reliefconductorwidth=10 reliefentries=4 polygonreliefangle="90 Angle" airgapwidth=8
PolygonConnect PolygonConnect_DIP [InComponentClass('DIP') vs InNet('GND')] p2: thpad.connectstyle=Relief thpad.reliefconductorwidth=20 thpad.reliefentries=4 thpad.polygonreliefangle="90 Angle" thpad.airgapwidth=10 smdpad.connectstyle=Direct smdpad.reliefconductorwidth=20 smdpad.reliefentries=4 smdpad.polygonreliefangle="90 Angle" smdpad.airgapwidth=10 via.connectstyle=Direct via.reliefconductorwidth=15 via.reliefentries=4 via.polygonreliefangle="90 Angle" via.airgapwidth=10
PolygonConnect [All] p3: connectstyle=Direct reliefconductorwidth=10 reliefentries=4 polygonreliefangle="90 Angle" airgapwidth=10
RoutingVias RoutingVias_U20 [InComponent('U20')] p1: holewidth=12 width=24 viastyle="Through Hole" minholewidth=12 minwidth=24 maxholewidth=12 maxwidth=24
RoutingVias RoutingVias_Q1-Q4 [InComponentClass('Q1-Q4')] p2: holewidth=6 width=14 viastyle="Through Hole" minholewidth=6 minwidth=14 maxholewidth=28 maxwidth=50
RoutingVias [All] p3: holewidth=10 width=16 viastyle="Through Hole" minholewidth=8 minwidth=16 maxholewidth=12 maxwidth=22
SilkToSilkClearance [All] p1 off: silktosilkclearance=10
SilkToSolderMaskClearance [IsPad] p1 off: minsilkscreentomaskgap=10 clearancetoexposedcopper=TRUE
SolderMaskExpansion [All] p1: expansion=2.36 istentingtop=FALSE
SupplyNets "Schematic Supply Nets_53" [InNet('LS_12V')] p1: voltage=0.000
SupplyNets "Schematic Supply Nets_52" [InNet('CSI_HV')] p2: voltage=0.000
SupplyNets "Schematic Supply Nets_19" [InNet('DP_HV')] p3: voltage=0.000
SupplyNets "Schematic Supply Nets_51" [InNet('VDD_CSI_5V_C')] p4: voltage=0.000
SupplyNets "Schematic Supply Nets_50" [InNet('VDD_3V3_C')] p5: voltage=0.000
SupplyNets "Schematic Supply Nets_49" [InNet('VDD_CSI_5V_D')] p6: voltage=0.000
SupplyNets "Schematic Supply Nets_48" [InNet('VDD_CSI_5V')] p7: voltage=0.000
SupplyNets "Schematic Supply Nets_47" [InNet('VDD_3V3_A')] p8: voltage=0.000
SupplyNets "Schematic Supply Nets_46" [InNet('VDD_CSI_5V_A')] p9: voltage=0.000
SupplyNets "Schematic Supply Nets_45" [InNet('VDD_3V3_D')] p10: voltage=0.000
SupplyNets "Schematic Supply Nets_44" [InNet('VDD_3V3_B')] p11: voltage=0.000
SupplyNets "Schematic Supply Nets_43" [InNet('VDD_CSI_5V_B')] p12: voltage=0.000
SupplyNets "Schematic Supply Nets_42" [InNet('PER_12V')] p13: voltage=0.000
SupplyNets "Schematic Supply Nets_41" [InNet('VBUS_5V0_TYPEC_A')] p14: voltage=0.000
SupplyNets "Schematic Supply Nets_40" [InNet('VDD_2V5')] p15: voltage=0.000
SupplyNets "Schematic Supply Nets_39" [InNet('VDD_SD')] p16: voltage=0.000
SupplyNets "Schematic Supply Nets_38" [InNet('VSYS_3V3')] p17: voltage=0.000
SupplyNets "Schematic Supply Nets_37" [InNet('RTC_PWR')] p18: voltage=0.000
SupplyNets "Schematic Supply Nets_36" [InNet('GND_CHASE')] p19: voltage=0.000
SupplyNets "Schematic Supply Nets_35" [InNet('LDO_1V5')] p20: voltage=0.000
SupplyNets "Schematic Supply Nets_34" [InNet('SDIO_A_IOPWR')] p21: voltage=0.000
SupplyNets "Schematic Supply Nets_33" [InNet('GND_DC')] p22: voltage=0.000
SupplyNets "Schematic Supply Nets_32" [InNet('VDDD')] p23: voltage=0.000
SupplyNets "Schematic Supply Nets_31" [InNet('SDIO_B_IOPWR')] p24: voltage=0.000
SupplyNets "Schematic Supply Nets_30" [InNet('AUD_3V3')] p25: voltage=0.000
SupplyNets "Schematic Supply Nets_29" [InNet('VDD_OSM_0_3V3')] p26: voltage=0.000
SupplyNets "Schematic Supply Nets_28" [InNet('GND')] p27: voltage=0.000
SupplyNets "Schematic Supply Nets_27" [InNet('VDD_M2_SIDEBAND')] p28: voltage=0.000
SupplyNets "Schematic Supply Nets_26" [InNet('AGND')] p29: voltage=0.000
SupplyNets "Schematic Supply Nets_25" [InNet('ENET_1V0')] p30: voltage=0.000
SupplyNets "Schematic Supply Nets_24" [InNet('ETH0_VDDA_1V0')] p31: voltage=0.000
SupplyNets "Schematic Supply Nets_23" [InNet('VDD_5V')] p32: voltage=0.000
SupplyNets "Schematic Supply Nets_22" [InNet('V_SYS')] p33: voltage=0.000
SupplyNets "Schematic Supply Nets_21" [InNet('USB_DBG')] p34: voltage=0.000
SupplyNets "Schematic Supply Nets_20" [InNet('ETH1_VDDA_1V0')] p35: voltage=0.000
SupplyNets "Schematic Supply Nets_18" [InNet('LDO_3V3')] p36: voltage=0.000
SupplyNets "Schematic Supply Nets_17" [InNet('V_REGN')] p37: voltage=0.000
SupplyNets "Schematic Supply Nets_16" [InNet('V_BAT')] p38: voltage=0.000
SupplyNets "Schematic Supply Nets_15" [InNet('VDDA')] p39: voltage=0.000
SupplyNets "Schematic Supply Nets_14" [InNet('VDD_SD_3V3')] p40: voltage=0.000
SupplyNets "Schematic Supply Nets_13" [InNet('VDD_3V3_SDIO_B')] p41: voltage=0.000
SupplyNets "Schematic Supply Nets_12" [InNet('VDD_1V8')] p42: voltage=0.000
SupplyNets "Schematic Supply Nets_11" [InNet('VDD_OSM_S_M_5V')] p43: voltage=0.000
SupplyNets "Schematic Supply Nets_10" [InNet('ETH1_VDDA_2V5')] p44: voltage=0.000
SupplyNets "Schematic Supply Nets_9" [InNet('VBUS_5V0_TYPEC_C')] p45: voltage=0.000
SupplyNets "Schematic Supply Nets_8" [InNet('VSYS_5V')] p46: voltage=0.000
SupplyNets "Schematic Supply Nets_7" [InNet('ETH0_VDDA_2V5')] p47: voltage=0.000
SupplyNets "Schematic Supply Nets_6" [InNet('ETH1_VDDA_1V8')] p48: voltage=0.000
SupplyNets "Schematic Supply Nets_5" [InNet('V_SYS2')] p49: voltage=0.000
SupplyNets "Schematic Supply Nets_4" [InNet('VPD_output')] p50: voltage=0.000
SupplyNets "Schematic Supply Nets_3" [InNet('VBUS_5V0_TYPEC_D')] p51: voltage=0.000
SupplyNets "Schematic Supply Nets_2" [InNet('VDD_OSM_1V8')] p52: voltage=0.000
SupplyNets "Schematic Supply Nets_1" [InNet('VDD_3V3_M2')] p53: voltage=0.000
SupplyNets "Schematic Supply Nets" [InNet('VDD_3V3')] p54: voltage=0.000
UnRoutedNet [All] p1: checkbadconnections=TRUE
Width Width_EMMC [InNetClass('EMMC')] p1: maxlimit=8.5 minlimit=2.61 preferedwidth=8.5 toplayer_minwidth=6 toplayer_maxwidth=6 toplayer_prefwidth=6 midlayer1_minwidth=4 midlayer1_maxwidth=4 midlayer1_prefwidth=4 midlayer2_minwidth=8.5 midlayer3_minwidth=8.5 midlayer4_maxwidth=2.61 midlayer4_prefwidth=2.61 midlayer5_minwidth=4 midlayer5_maxwidth=4 midlayer5_prefwidth=4 midlayer6_maxwidth=2.61 midlayer6_prefwidth=2.61 bottomlayer_minwidth=6 bottomlayer_maxwidth=6 bottomlayer_prefwidth=6 impedanceprofiledriven=TRUE impedanceprofileid={F9D28BC9-16DF-4F42-A987-31C794AAA2C4} impedanceprofilevalue=50.000000 minimp=50.000000 maximp=50.000000 favimp=50.000000
Width Width_QSPI [InNetClass('SPI_B') OR InNetClass('SPI_C')  OR InNetClass('SPI_A')] p2: maxlimit=8.5 minlimit=2.61 preferedwidth=8.5 toplayer_minwidth=6 toplayer_maxwidth=6 toplayer_prefwidth=6 midlayer1_minwidth=5 midlayer1_maxwidth=5 midlayer1_prefwidth=5 midlayer2_minwidth=8.5 midlayer3_minwidth=8.5 midlayer4_maxwidth=2.61 midlayer4_prefwidth=2.61 midlayer5_minwidth=5 midlayer5_maxwidth=5 midlayer5_prefwidth=5 midlayer6_maxwidth=2.61 midlayer6_prefwidth=2.61 bottomlayer_minwidth=6 bottomlayer_maxwidth=6 bottomlayer_prefwidth=6 impedanceprofiledriven=TRUE impedanceprofileid={2C1BAB26-653F-4B1A-B083-91D21490996D} impedanceprofilevalue=50.000000 minimp=50.000000 maximp=50.000000 favimp=50.000000
Width Width_SDIO [InNetClass('SDIO_ALL')] p3: maxlimit=8.5 minlimit=2.61 preferedwidth=8.5 toplayer_minwidth=6 toplayer_maxwidth=6 toplayer_prefwidth=6 midlayer1_minwidth=4 midlayer1_maxwidth=4 midlayer1_prefwidth=4 midlayer2_minwidth=8.5 midlayer3_minwidth=8.5 midlayer4_maxwidth=2.61 midlayer4_prefwidth=2.61 midlayer5_minwidth=4 midlayer5_maxwidth=4 midlayer5_prefwidth=4 midlayer6_maxwidth=2.61 midlayer6_prefwidth=2.61 bottomlayer_minwidth=6 bottomlayer_maxwidth=6 bottomlayer_prefwidth=6 impedanceprofiledriven=TRUE impedanceprofileid={F9D28BC9-16DF-4F42-A987-31C794AAA2C4} impedanceprofilevalue=50.000000 minimp=50.000000 maximp=50.000000 favimp=50.000000
Width Width_ETH_A [InNetClass('ETH_ALL')] p4: maxlimit=8.5 minlimit=2.61 preferedwidth=8.5 toplayer_minwidth=6 toplayer_maxwidth=6 toplayer_prefwidth=6 midlayer1_minwidth=3.95 midlayer1_maxwidth=3.95 midlayer1_prefwidth=3.95 midlayer2_minwidth=8.5 midlayer3_minwidth=8.5 midlayer4_maxwidth=2.61 midlayer4_prefwidth=2.61 midlayer5_minwidth=3.95 midlayer5_maxwidth=3.95 midlayer5_prefwidth=3.95 midlayer6_maxwidth=2.61 midlayer6_prefwidth=2.61 bottomlayer_minwidth=6 bottomlayer_maxwidth=6 bottomlayer_prefwidth=6 impedanceprofiledriven=TRUE impedanceprofileid={DE6DC93C-5E82-461D-954E-220478CD9314} impedanceprofilevalue=50.000000 minimp=50.000000 maximp=50.000000 favimp=50.000000
Width [All] p5: maxlimit=120 minlimit=4 preferedwidth=5
24 further rules are at their usual default settings.

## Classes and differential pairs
net class SPI_A: SPI_A_/HOLD_(IO3) SPI_A_/WP_(IO2) SPI_A_SCK SPI_A_SDI_(IO1) SPI_A_SDO_(IO0)
component class 940-00384[History]: PCB1
net class Class_LVDS_E: eDP_B_AUX_N/LVDS_E_CLK_N eDP_B_AUX_P/LVDS_E_CLK_P eDP_B_LANE0_N/LVDS_E_LANE0_N eDP_B_LANE0_P/LVDS_E_LANE0_P eDP_B_LANE1_N/LVDS_E_LANE1_N eDP_B_LANE1_P/LVDS_E_LANE1_P eDP_B_LANE2_N/LVDS_E_LANE2_N eDP_B_LANE2_P/LVDS_E_LANE2_P eDP_B_LANE3_N/LVDS_E_LANE3_N eDP_B_LANE3_P/LVDS_E_LANE3_P
net class Class_LVDS_D: eDP_A_AUX_N/LVDS_D_CLK_N eDP_A_AUX_P/LVDS_D_CLK_P eDP_A_LANE0_N/LVDS_D_LANE0_N eDP_A_LANE0_P/LVDS_D_LANE0_P eDP_A_LANE1_N/LVDS_D_LANE1_N eDP_A_LANE1_P/LVDS_D_LANE1_P eDP_A_LANE2_N/LVDS_D_LANE2_N eDP_A_LANE2_P/LVDS_D_LANE2_P eDP_A_LANE3_N/LVDS_D_LANE3_N eDP_A_LANE3_P/LVDS_D_LANE3_P
net class Class_CSI_A: CSI_A_CLOCK_N CSI_A_CLOCK_P CSI_A_DATA0_N CSI_A_DATA0_P CSI_A_DATA1_N CSI_A_DATA1_P CSI_A_DATA2_N CSI_A_DATA2_P CSI_A_DATA3_N CSI_A_DATA3_P
net class Class_CSI_B: CSI_B_CLOCK_N CSI_B_CLOCK_P CSI_B_DATA0_N CSI_B_DATA0_P CSI_B_DATA1_N CSI_B_DATA1_P CSI_B_DATA2_N CSI_B_DATA2_P CSI_B_DATA3_N CSI_B_DATA3_P
net class Class_CSI_C: CSI_C_CLOCK_N CSI_C_CLOCK_P CSI_C_DATA0_N CSI_C_DATA0_P CSI_C_DATA1_N CSI_C_DATA1_P CSI_C_DATA2_N CSI_C_DATA2_P CSI_C_DATA3_N CSI_C_DATA3_P
net class Class_CSI_D: CSI_D_CLOCK_N CSI_D_CLOCK_P CSI_D_DATA0_N CSI_D_DATA0_P CSI_D_DATA1_N CSI_D_DATA1_P CSI_D_DATA2_N CSI_D_DATA2_P CSI_D_DATA3_N CSI_D_DATA3_P
net class Class_MIPI_DSI_LVDS_A: "DSI_A_CLOCK_N / LVDS_A_CLK_N" "DSI_A_CLOCK_P / LVDS_A_CLK_P" "DSI_A_DATA0_N / LVDS_A_LANE0_N" "DSI_A_DATA0_P / LVDS_A_LANE0_P" "DSI_A_DATA1_N / LVDS_A_LANE1_N" "DSI_A_DATA1_P / LVDS_A_LANE1_P" "DSI_A_DATA2_N / LVDS_A_LANE2_N" "DSI_A_DATA2_P / LVDS_A_LANE2_P" "DSI_A_DATA3_N / LVDS_A_LANE3_N" "DSI_A_DATA3_P / LVDS_A_LANE3_P"
net class SPI_C: SPI_C_SCK SPI_C_SDI SPI_C_SDO
net class SPI_B: SPI_B_MCU_SCK SPI_B_MCU_SDI SPI_B_MCU_SDO
component class SMT: CON5 CON6 CON7 CON9 CON10 CON11 CON12 CON13 CON14 CON15 CON16 CON17 CON18
net class SDIO_uSD: NetC296_1 NetCON8_1 NetCON8_2 NetCON8_3 NetCON8_7 NetCON8_8 uSD_CLK uSD_CMD uSD_DATA0 uSD_DATA1 uSD_DATA2 uSD_DATA3
differential pair class "85 ohm": DIFF_M2_PCIE DIFF_M2_PCIE_CLK0 DIFF_M2_PCIE_HSI0_NET DIFF_PCIE_A_HSI0 DIFF_PCIE_A_HSO0 DIFF_PCIE_REFCLK
differential pair class "90 ohm": D_USBC_DATA_CONN D_USBC_SS_RX1_CONN D_USBC_SS_RX2_CONN D_USBC_SS_TX1_CONN D_USBC_SS_TX2_CONN DIFF DIFF_M2_USB1 DIFF_USB DIFF_USB_A_D DIFF_USB_B_D DIFF_USB_C_D DIFF_USB_C_SSRX DIFF_USB_C_SSTX DIFF_USB_D_D DIFF_USB_D_SSRX DIFF_USB_D_SSTX DIFF_USB_M2 DIFF_USBB_NetF DIFF_USBB_NetF1 DIFF_USBC DIFF_USBC_CONN DIFF_USBC_NET USB_FL5 USB_FL5_NET USB_FL6 USB_FL6_NET USB_FL7 USB_FL7_NET USB_FL8 USB_FL8_NET USB_FL10 USB_FL10_NET USB_FL11 USB_FL11_NET USB_FL12 USB_FL12_NET USB_FL13 USB_FL13_NET USB_FL15_NET USBC_DATA_CONN USBC_SS_RX1_CONN USBC_SS_RX2_CONN USBC_SS_TX1_CONN USBC_SS_TX2_CONN
differential pair class "100 ohm": DIFF_CSI_A DIFF_CSI_A_CLOCK DIFF_CSI_A_DATA0 DIFF_CSI_A_DATA1 DIFF_CSI_A_DATA2 DIFF_CSI_A_DATA3 DIFF_CSI_B_CLOCK DIFF_CSI_B_DATA0 DIFF_CSI_B_DATA1 DIFF_CSI_B_DATA2 DIFF_CSI_B_DATA3 DIFF_CSI_B_TX DIFF_CSI_C_CLOCK DIFF_CSI_C_DATA0 DIFF_CSI_C_DATA1 DIFF_CSI_C_DATA2 DIFF_CSI_C_DATA3 DIFF_CSI_D_CLOCK DIFF_CSI_D_DATA0 DIFF_CSI_D_DATA1 DIFF_CSI_D_DATA2 DIFF_CSI_D_DATA3 DIFF_DSI_A_CLOCK DIFF_DSI_A_DATA0 DIFF_DSI_A_DATA1 DIFF_DSI_A_DATA2 DIFF_DSI_A_DATA3 DIFF_ENET0_TRXA DIFF_ENET0_TRXB DIFF_ENET0_TRXC DIFF_ENET0_TRXD DIFF_ENET1_TRXA DIFF_ENET1_TRXB DIFF_ENET1_TRXC DIFF_ENET1_TRXD DIFF_LVDS_C_CLK DIFF_LVDS_C_LANE0 DIFF_LVDS_C_LANE1 DIFF_LVDS_C_LANE2 DIFF_LVDS_C_LANE3 DIFF_LVDS_D_CLK DIFF_LVDS_D_LANE0 DIFF_LVDS_D_LANE1 DIFF_LVDS_D_LANE2 DIFF_LVDS_D_LANE3 DIFF_LVDS_E_CLK DIFF_LVDS_E_LANE0 DIFF_LVDS_E_LANE1 DIFF_LVDS_E_LANE2 DIFF_LVDS_E_LANE3
component class "940-00384[OSM IO connector 1]": CON15 CON16 J17 TP20 TP36 TP38
component class Q1-Q4: Q1 Q2 Q3 Q4
component class DIP: C243 CON2 CON3 J1 J2 J3 J4 J5 J6 J7 J8 J9 J10 J11 J12 J13 J14 J16 J17 J18 J19 J20 J21 J22 J23 J24 J25 J26 J27 J28 J29 J31 J32 J33 J34 J35 J38 J39 J45 J46 J47 J48 J49 J51 J53 MH1 P1 P2 TP9 TP41 TP42 TP43
net class SDIO_M2_SD: M2_SD_CLK M2_SD_CMD M2_SD_DATA0 M2_SD_DATA1 M2_SD_DATA2 M2_SD_DATA3
net class SDIO_A: SDIO_A_CLK SDIO_A_CMD SDIO_A_D0 SDIO_A_D1 SDIO_A_D2 SDIO_A_D3
net class SDIO_B: SDIO_B_CLK SDIO_B_CMD SDIO_B_D0 SDIO_B_D1 SDIO_B_D2 SDIO_B_D3 SDIO_B_D4 SDIO_B_D5 SDIO_B_D6 SDIO_B_D7
net class RGB: RGB_B0 RGB_B1 RGB_B2 RGB_B3 RGB_B4 RGB_B5 RGB_G0 RGB_G1 RGB_G2 RGB_G3 RGB_G4 RGB_G5 RGB_R0 RGB_R1 RGB_R2 RGB_R3 RGB_R4 RGB_R5
component class "940-00384[I2C expander Display]": C223 C224 C225 C226 C227 C228 C405 C406 C407 C408 C409 C410 C411 C412 C413 C414 C415 C416 R211 R212 R213 R214 R215 R216 R217 R218 R219 R220 R234 R255 R348 R349 R402 R403 R404 R405 R491 R492 R493 R494 R495 R496 R497 R498 R499 R500 R501 R502 R503 R504 R505 R506 R507 R508 R509 R513 R514 SB5 SB6 U22 U58 U59 U60 U61
net class ETH_ALL: ETH_A_(R)(G)MII_RX_CLK ETH_A_(R)(G)MII_RXD2 ETH_A_(R)(G)MII_RXD3 ETH_A_(R)(G)MII_TX_CLK ETH_A_(S)(R)(G)MII_RXD0 ETH_A_(S)(R)(G)MII_RXD1 ETH_A_(S)(R)(G)MII_TXD0 ETH_A_(S)(R)(G)MII_TXD1 ETH_A_(S)(R)(G)MII_TXD2 ETH_A_(S)(R)(G)MII_TXD3 ETH_B_(R)(G)MII_RX_CLK ETH_B_(R)(G)MII_RXD2 ETH_B_(R)(G)MII_RXD3 ETH_B_(S)(R)(G)MII_RXD0 ETH_B_(S)(R)(G)MII_RXD1 ETH_B_(S)(R)(G)MII_TXD0 ETH_B_(S)(R)(G)MII_TXD1 ETH_B_(S)(R)(G)MII_TXD2 ETH_B_(S)(R)(G)MII_TXD3 PHY0_RX_CLK PHY0_RXD0 PHY0_RXD1 PHY0_RXD2 PHY0_RXD3 PHY1_RX_CLK PHY1_RXD0 PHY1_RXD1 PHY1_RXD2 PHY1_RXD3
net class SDIO_ALL: M2_SD_CLK M2_SD_CMD M2_SD_DATA0 M2_SD_DATA1 M2_SD_DATA2 M2_SD_DATA3 NetC296_1 NetCON8_1 NetCON8_2 NetCON8_3 NetCON8_7 NetCON8_8 NetR306_1 NetR307_1 NetR308_1 NetR310_1 NetR312_1 NetR314_1 SDIO_A_CLK SDIO_A_CMD SDIO_A_D0 SDIO_A_D1 SDIO_A_D2 SDIO_A_D3 uSD_CLK uSD_CMD uSD_DATA0 uSD_DATA1 uSD_DATA2 uSD_DATA3
net class USB: USB_A_D_N USB_A_D_P USB_B_D_N USB_B_D_P USB_C_D_N USB_C_D_P USB_C_SSRX_N USB_C_SSRX_P USB_C_SSTX_N USB_C_SSTX_P USB_D_D_N USB_D_D_P USB_D_SSRX_N USB_D_SSRX_P USB_D_SSTX_N USB_D_SSTX_P USBC_CC1_C USBC_CC1_D USBC_CC2_C USBC_CC2_D USBC_DATA_CONN_N_C USBC_DATA_CONN_N_D USBC_DATA_CONN_P_C USBC_DATA_CONN_P_D USBC_PWR_CC1 USBC_PWR_CC2 USBC_PWR_DATA_CONN_N USBC_PWR_DATA_CONN_P USBC_SS_RX1_CONN_N_C USBC_SS_RX1_CONN_N_D USBC_SS_RX1_CONN_P_C USBC_SS_RX1_CONN_P_D USBC_SS_RX2_CONN_N_C USBC_SS_RX2_CONN_N_D USBC_SS_RX2_CONN_P_C USBC_SS_RX2_CONN_P_D USBC_SS_TX1_CONN_N_C USBC_SS_TX1_CONN_N_D USBC_SS_TX1_CONN_P_C USBC_SS_TX1_CONN_P_D USBC_SS_TX2_CONN_N_C USBC_SS_TX2_CONN_N_D USBC_SS_TX2_CONN_P_C USBC_SS_TX2_CONN_P_D
net class ETH_B_RX: ETH_B_(R)(G)MII_RX_CLK ETH_B_(R)(G)MII_RXD2 ETH_B_(R)(G)MII_RXD3 ETH_B_(S)(R)(G)MII_RXD0 ETH_B_(S)(R)(G)MII_RXD1
net class ETH_A_RX: ETH_A_(R)(G)MII_RX_CLK ETH_A_(R)(G)MII_RXD2 ETH_A_(R)(G)MII_RXD3 ETH_A_(S)(R)(G)MII_RXD0 ETH_A_(S)(R)(G)MII_RXD1
net class ETH_B_TX: ETH_B_(R)(G)MII_TX_CLK ETH_B_(S)(R)(G)MII_TXD0 ETH_B_(S)(R)(G)MII_TXD1 ETH_B_(S)(R)(G)MII_TXD2 ETH_B_(S)(R)(G)MII_TXD3
net class ETH_RX_PHY1: PHY1_RX_CLK PHY1_RXD0 PHY1_RXD1 PHY1_RXD2 PHY1_RXD3
net class ETH_RX_PHY0: PHY0_RX_CLK PHY0_RXD0 PHY0_RXD1 PHY0_RXD2 PHY0_RXD3
net class ETH_A_TX: ETH_A_(R)(G)MII_TX_CLK ETH_A_(S)(R)(G)MII_TXD0 ETH_A_(S)(R)(G)MII_TXD1 ETH_A_(S)(R)(G)MII_TXD2 ETH_A_(S)(R)(G)MII_TXD3
net class EMMC: SDIO_B_D0 SDIO_B_D1 SDIO_B_D2 SDIO_B_D3 SDIO_B_D4 SDIO_B_D5 SDIO_B_D6 SDIO_B_D7
component class 940-00384[PWM_ADC_GPIO]: J28 J29
component class "940-00384[ETH GMAC0]": C118 C119 C120 C121 C122 C123 C124 C125 C126 C127 C128 C129 C130 C131 C132 C133 C134 C135 C136 C137 C138 C139 C140 C141 C142 C143 C263 CON2 D6 D7 D8 D9 FB1 FB2 J31 J32 J33 JMP31 JMP32 Q5 Q6 Q20 R76 R77 R78 R79 R80 R81 R82 R83 R84 R85 R86 R87 R88 R89 R90 R91 R92 R93 R94 R95 R96 R97 R98 R99 R100 R101 R102 R103 R104 R105 R106 R107 R108 R331 R570 TP10 TP11 TP12 TP13 U10 U44 Y1
net class QSPIBUS: SPI_A_/HOLD_(IO3) SPI_A_/WP_(IO2) SPI_A_CS0# SPI_A_SCK SPI_A_SDI_(IO1) SPI_A_SDO_(IO0)
net class ETH1BUS: ENET0_TRXA_N ENET0_TRXA_P ENET0_TRXB_N ENET0_TRXB_P ENET0_TRXC_N ENET0_TRXC_P ENET0_TRXD_N ENET0_TRXD_P
component class "940-00384[USB TypeC port A]": C71 C170 C171 C172 C173 C271 C272 D26 D29 FL3 L10 P1 R46 R47 R49 R142 R326 R557 R558 R559 R560 R561 R562 R563 R564 R565 R566 R567 TP26 U5 U12 U51
component class "940-00384[USB Type C Power]": C75 C76 C77 C78 C79 C80 C81 C82 C83 C84 C85 C86 C87 D1 D2 D3 F1 FL1 J1 J2 J37 J40 J41 J42 JMP40 JMP41 R51 R52 R53 R54 R55 R56 R57 R58 R59 R60 R61 R62 R63 R64 R210 R273 U7 U8
component class "940-00384[USB TypeC port D]": C183 C184 C185 C186 C187 C188 C189 C190 C191 C275 C316 C317 C318 C319 D16 D17 FL9 FL10 FL11 FL12 FL13 J5 R146 R162 R163 R164 R165 R166 R167 R168 R169 R170 R171 R172 R173 R174 R175 R341 R342 R343 R344 R345 U16 U17 U18 U62
component class "940-00384[USB TypeC port C]": C72 C174 C175 C176 C177 C178 C179 C180 C181 C182 C312 C313 C314 C315 D14 D15 FL4 FL5 FL6 FL7 FL8 J4 J38 R48 R145 R147 R148 R150 R151 R152 R153 R154 R155 R156 R157 R158 R159 R327 R336 R337 R338 R339 R340 U6 U13 U14 U15
component class 940-00384[UART]: C273 C274 C280 C281 C282 C283 C284 C285 C286 C287 C288 C289 C290 C423 D25 FB13 FB14 FL15 J12 J14 J18 J26 J50 J53 JMP53 P2 R287 R288 R290 R291 R292 R293 R294 R295 R296 R297 R298 R325 R401 R568 R569 R606 U29 U74
component class 940-00384[SPI]: J19 J27 J44 SB1
component class 940-00384[SDIO_B]: C310 C311 C353 C354 C355 C356 C357 C358 C359 C360 C361 C372 C373 R397 R398 R430 R431 R432 R433 R434 SB3 TP29 TP30 TP31 TP33 U49 U54
component class 940-00384[SDIO_A]: C262 C294 C295 C296 C297 C298 C299 CON8 D27 D28 R304 R305 R306 R307 R308 R309 R310 R311 R312 R313 R314 R315 R316 R317 R318 R319 R391 R392 R393 R395 R396 R406 R407 R412 R420 R421 R422 R423 R424 R429 R442 R450 R526 R527 R528 R529 R530 R532 R538 TP22 TP25 U32 U33 U37 U43
component class "940-00384[RGB Display]": C215 C216 C217 C218 CON7 J20
component class "940-00384[MIPI_LVDS Display]": C219 C376 C377 C378 C379 C380 C381 C382 C383 C384 C385 C386 CON6 CON13 CON14 J13 J16 SB2
component class "940-00384[Power Management_Peripheral]": C30 C31 C32 C33 C34 C35 C36 C37 C38 C39 C40 C41 C42 C43 C44 C45 C46 C47 C48 C49 C50 C51 C52 C53 C54 C55 C56 C57 C58 C59 C60 C61 C62 C63 C64 C65 C66 C67 C68 C69 C70 C270 C293 C305 C306 C307 C308 C309 C388 C389 FB15 FB16 FB17 FB18 L4 L5 L6 L7 L13 Q13 Q14 Q15 R27 R28 R30 R31 R32 R33 R34 R35 R36 R37 R38 R39 R40 R41 R42 R43 R44 R45 R143 R149 R161 R230 R231 R301 R451 R518 R524 R555 R556 TP24 TP40 U4 U36 U48
component class "940-00384[Power Management_OSM]": C1 C2 C3 C4 C5 C6 C7 C8 C9 C10 C11 C12 C13 C14 C15 C16 C17 C18 C19 C20 C21 C22 C23 C24 C25 C26 C27 C28 C29 L1 L2 L3 LED1 LED2 LED3 R1 R2 R3 R4 R5 R6 R7 R8 R9 R10 R11 R12 R13 R14 R15 R16 R17 R18 R19 R20 R21 R22 R23 R24 R25 R29 TP1 TP2 TP3 U1 U2 U3
component class "940-00384[OSM IO connector 2]": CON17 CON18 J21 J22 J52 TP23 TP34 TP35 TP37
component class "940-00384[M.2 connector]": C239 C240 C241 C242 C243 C244 C245 C246 C247 C248 C249 C250 C251 C252 C253 C321 C370 C371 CON5 D22 FL14 LED5 MH1 R26 R160 R236 R237 R238 R239 R240 R241 R242 R243 R244 R245 R246 R247 R248 R249 R250 R251 R254 R256 R257 R258 R259 R261 R262 R263 R264 R265 R266 R267 R268 R269 R270 R281 R283 R289 R299 R350 R352 R409 R425 R426 R441 R443 TP21 TP39 U26 U38
component class "940-00384[M2_Level Shifter_Detector]": C231 C232 C233 C234 C235 C236 C237 C238 C320 R222 R223 R224 R225 R226 R227 R228 R229 R232 R233 R300 R351 R444 R445 R446 R447 R448 R449 R515 R516 U23 U24 U25 X1
component class 940-00384[LED_Buttons_Boot]: C73 C364 C365 C366 J43 J51 LED8 LED10 MH2 MH3 MH4 MH5 MH6 MH7 MH8 MH9 MH10 MH11 MH12 MH13 MH14 MH15 Q17 Q18 Q19 R408 R410 R413 R414 R415 R417 R531 R533 R534 R535 R536 S3 S5 S6 S7 S8 SB4 TP41 TP42 TP43
component class 940-00384[JTAG_RTC_Power]: BAT1 C221 C300 J24 J47 Q16 R221 R235 R320 R321 R322 R323 R324 R366 R510 R517 R607 R608
component class "940-00384[IO expander]": C269 C302 C367 C368 C387 J36 JMP36 R209 R302 R303 R328 R329 R330 R332 R333 R334 R335 R416 R428 R440 R537 R539 R540 R541 R542 R543 R544 R545 R546 R547 R548 R549 R550 R551 R552 R553 R554 U21 U35 U47 U50
component class 940-00384[I2C]: C374 C375 C393 J25 R435 R436 R437 R472 R473 R474 R475 R476 R477 U53 U55
component class "940-00384[ETH GMAC1]": C144 C145 C146 C147 C148 C149 C150 C151 C152 C153 C154 C155 C156 C157 C158 C159 C160 C161 C162 C163 C164 C165 C166 C167 C168 C169 C267 CON3 D10 D11 D12 D13 FB3 FB4 J34 J35 JMP34 JMP35 Q7 Q8 Q21 R109 R110 R111 R112 R113 R114 R115 R116 R117 R118 R119 R120 R121 R122 R123 R124 R125 R126 R127 R128 R129 R130 R131 R132 R133 R134 R135 R136 R137 R138 R139 R140 R141 R427 R571 TP14 TP15 TP16 TP17 U11 U45 Y2
component class 940-00384[CSI]: C256 C257 C258 C259 C291 C292 C322 C323 C324 C325 C326 C327 C328 C329 C330 C331 C332 C333 C334 C335 C336 C337 C338 C339 C340 C341 C342 C343 C344 C345 C346 C347 C348 C349 C350 C351 C352 C362 C363 CON9 CON10 CON11 CON12 J23 J45 J46 J48 J49 L14 R285 R353 R359 R360 R367 R368 R369 R370 R371 R372 R373 R374 R375 R376 R377 R378 R379 R380 R381 R382 R383 R384 R385 R386 R387 R388 R389 R390 R572 R573 R574 R575 R576 R577 R578 R579 R580 R581 R582 R583 R584 R585 R586 R587 R588 R589 R590 R591 R592 R593 R594 R595 R596 R597 R598 U28 U30 U39 U40 U41 U64 U65 U66 U67 U68 U69 U70 U71
component class "940-00384[I2C expander Camera]": C74 C229 C230 C260 C301 C390 C391 C392 C394 C395 C396 C397 C398 C399 C400 C401 C402 C403 C404 J30 R394 R399 R400 R411 R452 R453 R454 R455 R456 R457 R458 R459 R460 R461 R462 R463 R464 R465 R466 R467 R468 R469 R470 R471 R478 R479 R480 R481 R482 R483 R484 R485 R486 R487 R488 R489 R490 R511 R512 R519 R520 R521 R522 R523 U31 U34 U42 U52 U56 U57
component class "940-00384[Charger & Coulomb Counter]": C88 C89 C90 C91 C92 C93 C94 C95 C96 C97 C98 C99 C100 C101 C102 C103 C104 C105 C106 C107 C108 C109 C110 C111 C112 C113 C114 C115 C116 C117 C304 C417 C418 C419 C420 C421 C422 CON1 D4 D5 FL2 J3 L8 L9 LED4 Q1 Q2 Q3 Q4 R65 R66 R67 R68 R69 R70 R71 R72 R73 R74 R75 R176 R193 R199 R200 R252 R253 R260 R271 R272 R278 R280 R525 R599 R600 R601 R602 R603 R604 R605 S1 S2 TP4 TP5 TP6 TP7 TP8 TP9 U9 U72 U73
component class "940-00384[CAN BUS]": C220 C222 C254 C255 C264 C265 C266 C277 C278 C279 D23 D24 FB9 J7 J8 J9 J10 J11 JMP7 JMP8 JMP10 JMP11 L11 L12 R275 R277 R279 R282 R284 R286 R354 R355 R356 R357 R358 R361 R362 R363 R364 R365 U27
component class 940-00384[AUDIO]: C192 C193 C194 C195 C196 C197 C198 C199 C200 C201 C202 C203 C204 C205 C206 C207 C208 C209 C210 C211 C212 C213 C214 C261 C268 C276 C303 C369 CON4 D18 D19 D20 D21 FB5 FB6 FB8 J6 J39 Q10 R50 R144 R177 R178 R179 R180 R181 R182 R183 R184 R185 R186 R187 R188 R189 R190 R191 R192 R194 R195 R196 R197 R198 R201 R202 R203 R204 R205 R206 R207 R208 R274 R276 R346 R347 R418 R419 U19 U20 U46 U63 X2
differential pair USB_FL3_NET: +NetFL3_A2 -NetFL3_A1
differential pair DIFF_CSI_A: +"CAM_A_SCL / CSI_A_TX_P" -"CAM_A_SDA / CSI_A_TX_N"
differential pair DIFF_CSI_B_TX: +"CAM_B_SCL / CSI_B_TX_P" -"CAM_B_SDA / CSI_B _TX_N"
differential pair DIFF_DSI_A_DATA0: +"DSI_A_DATA0_N / LVDS_A_LANE0_N" -"DSI_A_DATA0_P / LVDS_A_LANE0_P"
differential pair DIFF_DSI_A_DATA1: +"DSI_A_DATA1_N / LVDS_A_LANE1_N" -"DSI_A_DATA1_P / LVDS_A_LANE1_P"
differential pair DIFF_DSI_A_DATA2: +"DSI_A_DATA2_N / LVDS_A_LANE2_N" -"DSI_A_DATA2_P / LVDS_A_LANE2_P"
differential pair DIFF_DSI_A_DATA3: +"DSI_A_DATA3_N / LVDS_A_LANE3_N" -"DSI_A_DATA3_P / LVDS_A_LANE3_P"
differential pair DIFF_DSI_A_CLOCK: +"DSI_A_CLOCK_N / LVDS_A_CLK_N" -"DSI_A_CLOCK_P / LVDS_A_CLK_P"
differential pair DIFF_PCIE_A_HSI0: +PCIe_A_HSI0_P -PCIe_A_HSI0_N
differential pair USB_FL15_NET: +NetR325_2 -NetR401_2
differential pair DIFF_M2_PCIE_HSI0_NET: +NetCON5_43 -NetCON5_41
differential pair USB_FL12_NET: +NetR341_1 -NetR342_1
differential pair USB_FL12: +NetFL12_C1 -NetFL12_C2
differential pair USB_FL10_NET: +NetC316_1 -NetC317_1
differential pair USB_FL10: +NetC316_2 -NetC317_2
differential pair USB_FL13_NET: +NetR344_2 -NetR345_2
differential pair USB_FL13: +NetFL13_C1 -NetFL13_C2
differential pair USB_FL11_NET: +NetC318_1 -NetC319_1
differential pair USB_FL11: +NetC318_2 -NetC319_2
differential pair USB_FL7_NET: +NetR336_1 -NetR337_1
differential pair USB_FL5: +NetC312_2 -NetC313_2
differential pair USB_FL5_NET: +NetC312_1 -NetC313_1
differential pair USB_FL6_NET: +NetC314_1 -NetC315_1
differential pair USB_FL8: +NetFL8_C1 -NetFL8_C2
differential pair USB_FL8_NET: +NetR339_2 -NetR340_2
differential pair USB_FL6: +NetC314_2 -NetC315_2
differential pair USB_FL7: +NetFL7_C1 -NetFL7_C2
differential pair D_USBC_DATA_CONN: +USBC_DATA_CONN_N_C -USBC_DATA_CONN_P_C
differential pair D_USBC_SS_RX1_CONN: +USBC_SS_RX1_CONN_N_C -USBC_SS_RX1_CONN_P_C
differential pair D_USBC_SS_RX2_CONN: +USBC_SS_RX2_CONN_N_C -USBC_SS_RX2_CONN_P_C
differential pair D_USBC_SS_TX1_CONN: +USBC_SS_TX1_CONN_N_C -USBC_SS_TX1_CONN_P_C
differential pair D_USBC_SS_TX2_CONN: +USBC_SS_TX2_CONN_N_C -USBC_SS_TX2_CONN_P_C
differential pair USBC_DATA_CONN: +USBC_DATA_CONN_N_D -USBC_DATA_CONN_P_D
differential pair USBC_SS_RX1_CONN: +USBC_SS_RX1_CONN_N_D -USBC_SS_RX1_CONN_P_D
differential pair USBC_SS_RX2_CONN: +USBC_SS_RX2_CONN_N_D -USBC_SS_RX2_CONN_P_D
differential pair USBC_SS_TX1_CONN: +USBC_SS_TX1_CONN_N_D -USBC_SS_TX1_CONN_P_D
differential pair USBC_SS_TX2_CONN: +USBC_SS_TX2_CONN_N_D -USBC_SS_TX2_CONN_P_D
differential pair DIFF_USBB_NetF: +NetFL15_C1 -NetFL15_C2
differential pair DIFF_USBB_NetF1: +NetFL15_A2 -NetFL15_A1
differential pair DIFF_M2_PCIE: +NetC248_1 -NetC249_1
differential pair DIFF_USBC_NET: +NetR52_2 -NetR53_2
differential pair DIFF_USBC: +NetFL1_C1 -NetFL1_C2
differential pair DIFF_USBC_CONN: +USBC_PWR_DATA_CONN_P -USBC_PWR_DATA_CONN_N
differential pair DIFF_M2_USB1: +NetCON5_3 -NetCON5_5
differential pair DIFF_USB_M2: +M2_USB_D+ -M2_USB_D-
differential pair DIFF_USB: +NetFL3_A2 -NetFL3_A1
differential pair DIFF_LVDS_C_LANE0: +"" -""
differential pair DIFF_LVDS_C_LANE1: +"" -""
differential pair DIFF_LVDS_C_LANE2: +"" -""
differential pair DIFF_LVDS_C_LANE3: +"" -""
differential pair DIFF_LVDS_C_CLK: +"" -""
differential pair DIFF_LVDS_E_CLK: +eDP_B_AUX_P/LVDS_E_CLK_P -eDP_B_AUX_N/LVDS_E_CLK_N
differential pair DIFF_LVDS_E_LANE3: +eDP_B_LANE3_P/LVDS_E_LANE3_P -eDP_B_LANE3_N/LVDS_E_LANE3_N
differential pair DIFF_LVDS_E_LANE2: +eDP_B_LANE2_P/LVDS_E_LANE2_P -eDP_B_LANE2_N/LVDS_E_LANE2_N
differential pair DIFF_LVDS_E_LANE1: +eDP_B_LANE1_P/LVDS_E_LANE1_P -eDP_B_LANE1_N/LVDS_E_LANE1_N
differential pair DIFF_LVDS_E_LANE0: +eDP_B_LANE0_P/LVDS_E_LANE0_P -eDP_B_LANE0_N/LVDS_E_LANE0_N
differential pair DIFF_LVDS_D_CLK: +eDP_A_AUX_P/LVDS_D_CLK_P -eDP_A_AUX_N/LVDS_D_CLK_N
differential pair DIFF_LVDS_D_LANE3: +eDP_A_LANE3_P/LVDS_D_LANE3_P -eDP_A_LANE3_N/LVDS_D_LANE3_N
differential pair DIFF_LVDS_D_LANE2: +eDP_A_LANE2_P/LVDS_D_LANE2_P -eDP_A_LANE2_N/LVDS_D_LANE2_N
differential pair DIFF_LVDS_D_LANE1: +eDP_A_LANE1_P/LVDS_D_LANE1_P -eDP_A_LANE1_N/LVDS_D_LANE1_N
differential pair DIFF_LVDS_D_LANE0: +eDP_A_LANE0_P/LVDS_D_LANE0_P -eDP_A_LANE0_N/LVDS_D_LANE0_N
differential pair DIFF_M2_PCIE_CLK0: +NetCON5_49 -NetCON5_47
differential pair DIFF_CSI_A_CLOCK: +CSI_A_CLOCK_N -CSI_A_CLOCK_P
differential pair DIFF_CSI_A_DATA0: +CSI_A_DATA0_N -CSI_A_DATA0_P
differential pair DIFF_CSI_A_DATA1: +CSI_A_DATA1_N -CSI_A_DATA1_P
differential pair DIFF_CSI_A_DATA2: +CSI_A_DATA2_N -CSI_A_DATA2_P
differential pair DIFF_CSI_A_DATA3: +CSI_A_DATA3_N -CSI_A_DATA3_P
differential pair DIFF_CSI_B_CLOCK: +CSI_B_CLOCK_N -CSI_B_CLOCK_P
differential pair DIFF_CSI_B_DATA0: +CSI_B_DATA0_N -CSI_B_DATA0_P
differential pair DIFF_CSI_B_DATA1: +CSI_B_DATA1_N -CSI_B_DATA1_P
differential pair DIFF_CSI_B_DATA2: +CSI_B_DATA2_N -CSI_B_DATA2_P
differential pair DIFF_CSI_B_DATA3: +CSI_B_DATA3_N -CSI_B_DATA3_P
differential pair DIFF_CSI_C_CLOCK: +CSI_C_CLOCK_N -CSI_C_CLOCK_P
differential pair DIFF_CSI_C_DATA0: +CSI_C_DATA0_N -CSI_C_DATA0_P
differential pair DIFF_CSI_C_DATA1: +CSI_C_DATA1_N -CSI_C_DATA1_P
differential pair DIFF_CSI_C_DATA2: +CSI_C_DATA2_N -CSI_C_DATA2_P
differential pair DIFF_CSI_C_DATA3: +CSI_C_DATA3_N -CSI_C_DATA3_P
differential pair DIFF_CSI_D_CLOCK: +CSI_D_CLOCK_N -CSI_D_CLOCK_P
differential pair DIFF_CSI_D_DATA0: +CSI_D_DATA0_N -CSI_D_DATA0_P
differential pair DIFF_CSI_D_DATA1: +CSI_D_DATA1_N -CSI_D_DATA1_P
differential pair DIFF_CSI_D_DATA2: +CSI_D_DATA2_N -CSI_D_DATA2_P
differential pair DIFF_CSI_D_DATA3: +CSI_D_DATA3_N -CSI_D_DATA3_P
differential pair DIFF_ENET0_TRXA: +ENET0_TRXA_P -ENET0_TRXA_N
differential pair DIFF_ENET0_TRXB: +ENET0_TRXB_P -ENET0_TRXB_N
differential pair DIFF_ENET0_TRXC: +ENET0_TRXC_P -ENET0_TRXC_N
differential pair DIFF_ENET0_TRXD: +ENET0_TRXD_P -ENET0_TRXD_N
differential pair DIFF_ENET1_TRXA: +ENET1_TRXA_N -ENET1_TRXA_P
differential pair DIFF_ENET1_TRXB: +ENET1_TRXB_N -ENET1_TRXB_P
differential pair DIFF_ENET1_TRXC: +ENET1_TRXC_N -ENET1_TRXC_P
differential pair DIFF_ENET1_TRXD: +ENET1_TRXD_N -ENET1_TRXD_P
differential pair DIFF_PCIE_A_HSO0: +PCIe_A_HSO0_N -PCIe_A_HSO0_P
differential pair DIFF_PCIE_REFCLK: +PCIe_REFCLK_N -PCIe_REFCLK_P
differential pair DIFF_USB_B_D: +USB_B_D_N -USB_B_D_P
differential pair DIFF_USB_A_D: +USB_A_D_N -USB_A_D_P
differential pair DIFF_USB_C_D: +USB_C_D_N -USB_C_D_P
differential pair DIFF_USB_C_SSRX: +USB_C_SSRX_N -USB_C_SSRX_P
differential pair DIFF_USB_C_SSTX: +USB_C_SSTX_N -USB_C_SSTX_P
differential pair DIFF_USB_D_D: +USB_D_D_N -USB_D_D_P
differential pair DIFF_USB_D_SSRX: +USB_D_SSRX_N -USB_D_SSRX_P
differential pair DIFF_USB_D_SSTX: +USB_D_SSTX_N -USB_D_SSTX_P

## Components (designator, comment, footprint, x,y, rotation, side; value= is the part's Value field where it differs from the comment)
BAT1 "Adam Tech, BH-44F-5" "Adam Tech, BH-44F-5" 2798.66,1395.45 r270 bottom locked value=BH-44F-5
C1 "1206, 10uF, 50V" "CAP, 1206, 1.8mm, HD" 2303.6,425 r0 top value=10uF
C2 "1206, 10uF, 50V" "CAP, 1206, 1.8mm, HD" 2778,489.75 r180 top value=10uF
C3 "0805, 1uF, 50V" "CAP, 0805, 1.45mm, HD" 2318.72,497.25 r180 top value=1uF
C4 "0402, 47nF, 25V" "Chip. 0402, RF" 2348.98,665.99 r270 top value=47nF
C5 "0402, 22pF, 50V" "Chip. 0402, RF" 2502.12,707.62 r0 top value=22pF
C6 "1206, 22uF, 10V" "CAP, 1206, 1.8mm, HD" 2353.25,972.15 r0 top value=22uF
C7 "1206, 22uF, 10V" "CAP, 1206, 1.8mm, HD" 2142.36,1027.65 r90 top value=22uF
C8 "0805, 10uF, 50V" "CAP, 0805, 1.45mm, HD" 2337.11,345.91 r0 top value=10uF
C9 "0402, 47nF, 25V" "Chip. 0402, RF" 2682.31,313.24 r90 top value=47nF
C10 "0402, 22pF, 50V" "Chip. 0402, RF" 2539.37,230.08 r180 top value=22pF
C11 "1206, 22uF, 10V" "CAP, 1206, 1.8mm, HD" 3135.26,161.82 r0 top value=22uF
C12 "1206, 22uF, 10V" "CAP, 1206, 1.8mm, HD" 3136.11,251.26 r0 top value=22uF
C13 "0402, 22pF, 50V" "Chip. 0402, RF" 2418.7,720.81 r270 top value=22pF
C14 "0402, 2.2nF, 25V" "Chip. 0402, RF" 2452.58,720.93 r270 top value=2.2nF
C15 "0402, 22pF, 50V" "Chip. 0402, RF" 2619.66,252.08 r90 top value=22pF
C16 "0402, 3.3nF, 16V" "Chip. 0402, RF" 2586.77,251.82 r90 top value=3.3nF
C17 "0402, 22pF, 50V" "Chip. 0402, RF" 2647.31,719.76 r270 top value=22pF
C18 "0402, 3.3nF, 16V" "Chip. 0402, RF" 2613.24,719.76 r270 top value=3.3nF
C19 "0402, 10nF, 50V" "Chip. 0402, RF" 2409.27,650.75 r270 top value=10nF
C20 "0402, 47nF, 25V" "Chip. 0402, RF" 2709.93,667.6 r270 top value=47nF
C21 "0402, 10nF, 50V" "Chip. 0402, RF" 2629.25,322.98 r90 top value=10nF
C22 "0402, 22pF, 50V" "Chip. 0402, RF" 2560.15,741.76 r180 top value=22pF
C23 "1206, 22uF, 10V" "CAP, 1206, 1.8mm, HD" 2983.72,988.28 r0 top value=22uF
C24 "1206, 22uF, 10V" "CAP, 1206, 1.8mm, HD" 2774.33,988.28 r180 top value=22uF
C25 "0402, 10nF, 50V" "Chip. 0402, RF" 2663.13,650.75 r270 top value=10nF
C26 "0402, 100nF, 50V" "Chip. 0402, RF" 3115.04,681.1 r90 bottom value=100nF
C27 "0402, 100nF, 50V" "Chip. 0402, RF" 2171.04,1268.73 r0 top value=100nF
C28 "0201, 220nF, 10V" "Cap, C0201, Height 0.3mm" 3121.5,600.1 r270 bottom value=220nF
C29 "0201, 220nF, 10V" "Cap, C0201, Height 0.3mm" 2154.11,1202 r270 top value=220nF
C30 "0805, 22uF, 25V" "CAP, 0805, 1.45mm, HD" 1375.03,1439.01 r90 top value=22uF
C31 "0402, 100nF, 50V" "Chip. 0402, RF" 1364.96,1521.45 r0 top value=100nF
C32 "0201, 0.1uF, 10V" "Cap, C0201, Height 0.3mm" 1189.35,1548.84 r0 top value=100nF
C33 "0402, 4.7nF, 25V" "Chip. 0402, RF" 1158.9,1689.91 r180 top value=4.7nF
C34 "0201, 0.1uF, 10V" "Cap, C0201, Height 0.3mm" 934.71,1511.75 r0 top value=100nF
C35 "1206, 22uF, 10V" "CAP, 1206, 1.8mm, HD" 910.06,1369.41 r180 top value=22uF
C36 "1206, 22uF, 10V" "CAP, 1206, 1.8mm, HD" 910.06,1456.24 r180 top value=22uF
C37 "0402, 4.7nF, 25V" "Chip. 0402, RF" 1570.63,1675.7 r0 top value=4.7nF
C38 "0402, 4.7nF, 25V" "Chip. 0402, RF" 1570.86,1894.5 r0 top value=4.7nF
C39 "0805, 22uF, 25V" "CAP, 0805, 1.45mm, HD" 1311.35,1439.49 r90 top value=22uF
C40 "0402, 100nF, 50V" "Chip. 0402, RF" 1364.92,1554.54 r0 top value=100nF
C41 "0201, 120pF, 50V" "Cap, C0201, Height 0.3mm" 980.18,1551.62 r270 top value=120pF
C42 "0201, 0.1uF, 10V" "Cap, C0201, Height 0.3mm" 1510.01,1546.47 r180 top value=100nF
C43 "0201, 0.1uF, 10V" "Cap, C0201, Height 0.3mm" 1758.14,1514.14 r180 top value=100nF
C44 "1206, 22uF, 10V" "CAP, 1206, 1.8mm, HD" 1783.57,1435.63 r0 top value=22uF
C45 "1206, 22uF, 10V" "CAP, 1206, 1.8mm, HD" 1783.56,1349.11 r0 top value=22uF
C46 "0805, 22uF, 25V" "CAP, 0805, 1.45mm, HD" 1326.56,1999.72 r270 bottom value=22uF
C47 "0201, 120pF, 50V" "Cap, C0201, Height 0.3mm" 1712.45,1553.04 r270 top value=120pF
C48 "0402, 100nF, 50V" "Chip. 0402, RF" 1293.5,1926.92 r180 bottom value=100nF
C49 "0201, 0.1uF, 10V" "Cap, C0201, Height 0.3mm" 1397.71,1927.84 r180 top value=100nF
C50 "0805, 1uF, 50V" "CAP, 0805, 1.45mm, HD" 1594.23,1845.79 r0 top value=1uF
C51 "0201, 0.1uF, 10V" "Cap, C0201, Height 0.3mm" 1897.49,2158.46 r180 top value=100nF
C52 "1206, 22uF, 10V" "CAP, 1206, 1.8mm, HD" 1921.22,2021.34 r0 top value=22uF
C53 "1206, 22uF, 10V" "CAP, 1206, 1.8mm, HD" 1921.01,2102.51 r0 top value=22uF
C54 "0603, 3.3uF, 10V" "Chip, 0603, RF" 1586.14,1792.35 r180 top value=3.3uF
C55 "0402, 4.7nF, 25V" "Chip. 0402, RF" 1570.18,1753.69 r0 top value=4.7nF
C56 "0402, 4.7nF, 25V" "Chip. 0402, RF" 1063.76,1653.96 r0 bottom value=4.7nF
C57 "0603, 10uF, 25V" "Chip, 0603, RF" 1586.36,1714.36 r0 top value=10uF
C58 "0201, 120pF, 50V" "Cap, C0201, Height 0.3mm" 1801.27,1941.78 r90 top value=120pF
C59 "0402, 22pF, 50V" "Chip. 0402, RF" 1167.67,1641.75 r270 bottom value=22pF
C60 "0402, 22pF, 50V" "Chip. 0402, RF" 1501.15,1932 r90 bottom value=22pF
C61 "0402, 4.7nF, 25V" "Chip. 0402, RF" 1604.41,1921.06 r180 bottom value=4.7nF
C62 "0402, 22pF, 50V" "Chip. 0402, RF" 1558.25,1640.58 r270 bottom value=22pF
C63 "0805, 22uF, 25V" "CAP, 0805, 1.45mm, HD" 1387.55,1999.72 r270 bottom value=22uF
C64 "0402, 4.7nF, 25V" "Chip. 0402, RF" 1662.18,1653.55 r180 bottom value=4.7nF
C65 "0402, 100nF, 50V" "Chip. 0402, RF" 1420.16,1925.57 r0 bottom value=100nF
C66 "0201, 0.1uF, 10V" "Cap, C0201, Height 0.3mm" 1314.75,1927.5 r0 top value=100nF
C67 "0201, 0.1uF, 10V" "Cap, C0201, Height 0.3mm" 815.24,2163.08 r0 top value=100nF
C68 "1206, 22uF, 10V" "CAP, 1206, 1.8mm, HD" 791.05,2017.77 r180 top value=22uF
C69 "1206, 22uF, 10V" "CAP, 1206, 1.8mm, HD" 792.51,2105.47 r180 top value=22uF
C70 "0201, 120pF, 50V" "Cap, C0201, Height 0.3mm" 911.63,1941.69 r90 top value=120pF
C71 "0201, 0.1uF, 10V" "Cap, C0201, Height 0.3mm" 3768.26,43.03 r90 bottom value=100nF
C72 "0201, 0.1uF, 10V" "Cap, C0201, Height 0.3mm" 2614.81,6233.52 r0 bottom value=100nF
C73 "0402, 100nF, 50V" "Chip. 0402, RF" 826.52,6140.38 r90 bottom value=100nF
C74 "0201, 0.1uF, 10V" "Cap, C0201, Height 0.3mm" 1720.55,5924.49 r90 bottom value=100nF
C75 "0402, 10uF, 10V" "Chip. 0402, RF" 544.29,996.05 r0 top value=10uF
C76 "0805, 1uF, 50V" "CAP, 0805, 1.45mm, HD" 494.56,1497.91 r0 bottom value=1uF
C77 "0805, 4.7uF, 50V" "CAP, 0805, 1.45mm, HD" 585.97,1383.38 r0 top value=4.7uF
C78 "0603, 100nF, 50V" "Chip, 0603, RF" 585.99,1327.86 r0 top value=100nF
C79 "0402, 10nF, 50V" "Chip. 0402, RF" 592.29,1287.04 r0 top value=10nF
C80 "0402, 10uF, 10V" "Chip. 0402, RF" 613.66,962.28 r0 top value=10uF
C81 "0402, 10uF, 10V" "Chip. 0402, RF" 718.76,960.42 r180 top value=10uF
C82 "0402, 330pF, 50V" "Chip. 0402, RF" 518.47,1130.38 r0 top value=330pF
C83 "0402, 330pF, 50V" "Chip. 0402, RF" 518.47,1162.31 r0 top value=330pF
C84 "0805, 10uF, 50V" "CAP, 0805, 1.45mm, HD" 753.4,1419.52 r180 top value=10uF
C85 "0805, 10uF, 50V" "CAP, 0805, 1.45mm, HD" 753.68,1353.8 r180 top value=10uF
C86 "0603, 100nF, 50V" "Chip, 0603, RF" 753.94,1296.05 r180 top value=100nF
C87 "0201, 0.1uF, 10V" "Cap, C0201, Height 0.3mm" 900.05,1164.92 r90 top value=100nF
C88 "0402, 1.0nF, 50V" "Chip. 0402, RF" 1441.74,316.08 r90 top value=1.0nF
C89 "0805, 10uF, 50V" "CAP, 0805, 1.45mm, HD" 1536.76,487.42 r270 top value=10uF
C90 "0603, 10uF, 25V" "Chip, 0603, RF" 1909.27,550.26 r270 top value=10uF
C91 "0603, 10uF, 25V" "Chip, 0603, RF" 1863.88,550.35 r270 top value=10uF
C92 "0402, 1.0nF, 50V" "Chip. 0402, RF" 1219.84,722.11 r270 top value=1.0nF
C93 "0603, 4.7µF, 16V" "Chip, 0603, RF" 1534.94,385.47 r270 top value=4.7µF
C94 "1206, 10uF, 50V" "CAP, 1206, 1.8mm, HD" 1465.79,474.49 r270 top value=10uF
C95 "0402, 100nF, 50V" "Chip. 0402, RF" 1584.51,496.23 r270 top value=100nF
C96 "0402, 47nF, 25V" "Chip. 0402, RF" 1640.77,498.37 r90 bottom value=47nF
C97 "0402, 47nF, 25V" "Chip. 0402, RF" 1791.09,497.46 r90 bottom value=47nF
C98 "0805, 4.7uF, 50V" "CAP, 0805, 1.45mm, HD" 1307.11,924.55 r180 top value=4.7uF
C99 "0805, 10uF, 50V" "CAP, 0805, 1.45mm, HD" 1550.67,699.12 r0 top value=10uF
C100 "0805, 10uF, 50V" "CAP, 0805, 1.45mm, HD" 1550.67,763.23 r0 top value=10uF
C101 "0402, 100nF, 50V" "Chip. 0402, RF" 1755.6,607.96 r180 top value=100nF
C102 "0805, 10uF, 50V" "CAP, 0805, 1.45mm, HD" 1913.17,630.8 r180 bottom value=10uF
C103 "0805, 10uF, 50V" "CAP, 0805, 1.45mm, HD" 1913.93,694.4 r180 bottom value=10uF
C104 "0805, 10uF, 50V" "CAP, 0805, 1.45mm, HD" 1914.1,756.42 r180 bottom value=10uF
C105 "0805, 10uF, 50V" "CAP, 0805, 1.45mm, HD" 1913.93,694.4 r180 top value=10uF
C106 "0805, 10uF, 50V" "CAP, 0805, 1.45mm, HD" 1912.94,630.8 r180 top value=10uF
C107 "0805, 10uF, 50V" "CAP, 0805, 1.45mm, HD" 1550.67,635.55 r0 top value=10uF
C108 "0402, 100nF, 50V" "Chip. 0402, RF" 1680.05,608.11 r0 top value=100nF
C109 "0402, 1.0nF, 50V" "Chip. 0402, RF" 1861.87,555.47 r0 bottom value=1.0nF
C110 "0805, 1uF, 50V" "CAP, 0805, 1.45mm, HD" 958.15,170.26 r270 top value=1uF
C111 "1206, 10uF, 50V" "CAP, 1206, 1.8mm, HD" 872.66,155.74 r270 top value=10uF
C112 "1206, 10uF, 50V" "CAP, 1206, 1.8mm, HD" 1200.86,358.65 r90 top value=10uF
C113 "0805, 1uF, 50V" "CAP, 0805, 1.45mm, HD" 1216.81,130.62 r270 top value=1uF
C114 "0603, 47nF, 25V" "Chip, 0603, RF" 1277.83,131.6 r270 top value=47nF
C115 "Radial Can,100uF, 50V" "CAP, CAPAE, 10.5mm Dia." 944.05,623.07 r90 top value=100uF
C116 "0805, 4.7uF, 50V" "CAP, 0805, 1.45mm, HD" 1997.03,77.75 r270 top value=4.7uF
C117 "0805, 10uF, 50V" "CAP, 0805, 1.45mm, HD" 1930.42,76.92 r270 top value=10uF
C118 "0201, 1uF, 10V" "Cap, C0201, Height 0.3mm" 1352.63,3242.49 r90 top value=1uF
C119 "0201, 1uF, 10V" "Cap, C0201, Height 0.3mm" 1417.61,3272.58 r180 top value=1uF
C120 "0201, 0.1uF, 10V" "Cap, C0201, Height 0.3mm" 1417.43,3297.92 r0 top value=100nF
C121 "0201, 1000pF, 25V" "Cap, C0201, Height 0.3mm" 1446.25,3457.7 r180 bottom value=1000pF
C122 "0201, 100pF, 50V" "Cap, C0201, Height 0.3mm" 1395.32,3558.47 r270 bottom value=100pF
C123 "0201, 22pF, 50V" "Cap, C0201, Height 0.3mm" 1557.78,3492.99 r180 bottom value=22pF
C124 "0201, 470pF, 25V" "Cap, C0201, Height 0.3mm" 1459.11,3671.99 r90 top value=470pF
C125 "0201, 470pF, 25V" "Cap, C0201, Height 0.3mm" 1427.78,3671.99 r90 top value=470pF
C126 "0201, 1uF, 10V" "Cap, C0201, Height 0.3mm" 1174.62,3714.82 r0 top value=1uF
C127 "0201, 0.1uF, 10V" "Cap, C0201, Height 0.3mm" 1174.62,3689.91 r180 top value=100nF
C128 "0201, 1000pF, 25V" "Cap, C0201, Height 0.3mm" 1199.44,3266.62 r270 top value=1000pF
C129 "0201, 100pF, 50V" "Cap, C0201, Height 0.3mm" 1174.62,3664.62 r180 top value=100pF
C130 "0201, 100pF, 50V" "Cap, C0201, Height 0.3mm" 1223.5,3266.6 r270 top value=100pF
C131 "0201, 1uF, 10V" "Cap, C0201, Height 0.3mm" 1245.76,3404.29 r180 bottom value=1uF
C132 "0201, 1000pF, 25V" "Cap, C0201, Height 0.3mm" 1245.34,3546.91 r0 bottom value=1000pF
C133 "0201, 1000pF, 25V" "Cap, C0201, Height 0.3mm" 1245.34,3429.77 r0 bottom value=1000pF
C134 "0201, 1uF, 10V" "Cap, C0201, Height 0.3mm" 1402.12,3672 r270 top value=1uF
C135 "0201, 0.1uF, 10V" "Cap, C0201, Height 0.3mm" 1446.25,3492.99 r180 bottom value=100nF
C136 "0201, 1000pF, 25V" "Cap, C0201, Height 0.3mm" 1483.64,3305.19 r0 top value=1000pF
C137 "0201, 1000pF, 25V" "Cap, C0201, Height 0.3mm" 1244.87,3485.85 r0 bottom value=1000pF
C138 "0402, 220nF, 16V" "Chip. 0402, RF" 893.57,3729.06 r270 top value=220nF
C139 "0201, 10nF, 10V" "Cap, C0201, Height 0.3mm" 1371.42,3671.99 r90 top value=10nF
C140 "1206, 1000pF, 2kV" "CAP, 1206, 1.8mm, HD" 572.62,3982.23 r90 top value=1000pF
C141 "0201, 1uF, 10V" "Cap, C0201, Height 0.3mm" 905.69,3984.27 r90 top value=1uF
